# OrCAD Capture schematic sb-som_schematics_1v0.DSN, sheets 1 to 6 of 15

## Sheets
1 09. Ethernet & Camera: size C; title: SB-SOM    09. Ethernet & Camera; rev: 1.0; company: CompuLab Ltd.  (972) 4 8238567; note: 8000050000; note: P.O.Box 66; note: Nesher 36770, Israel
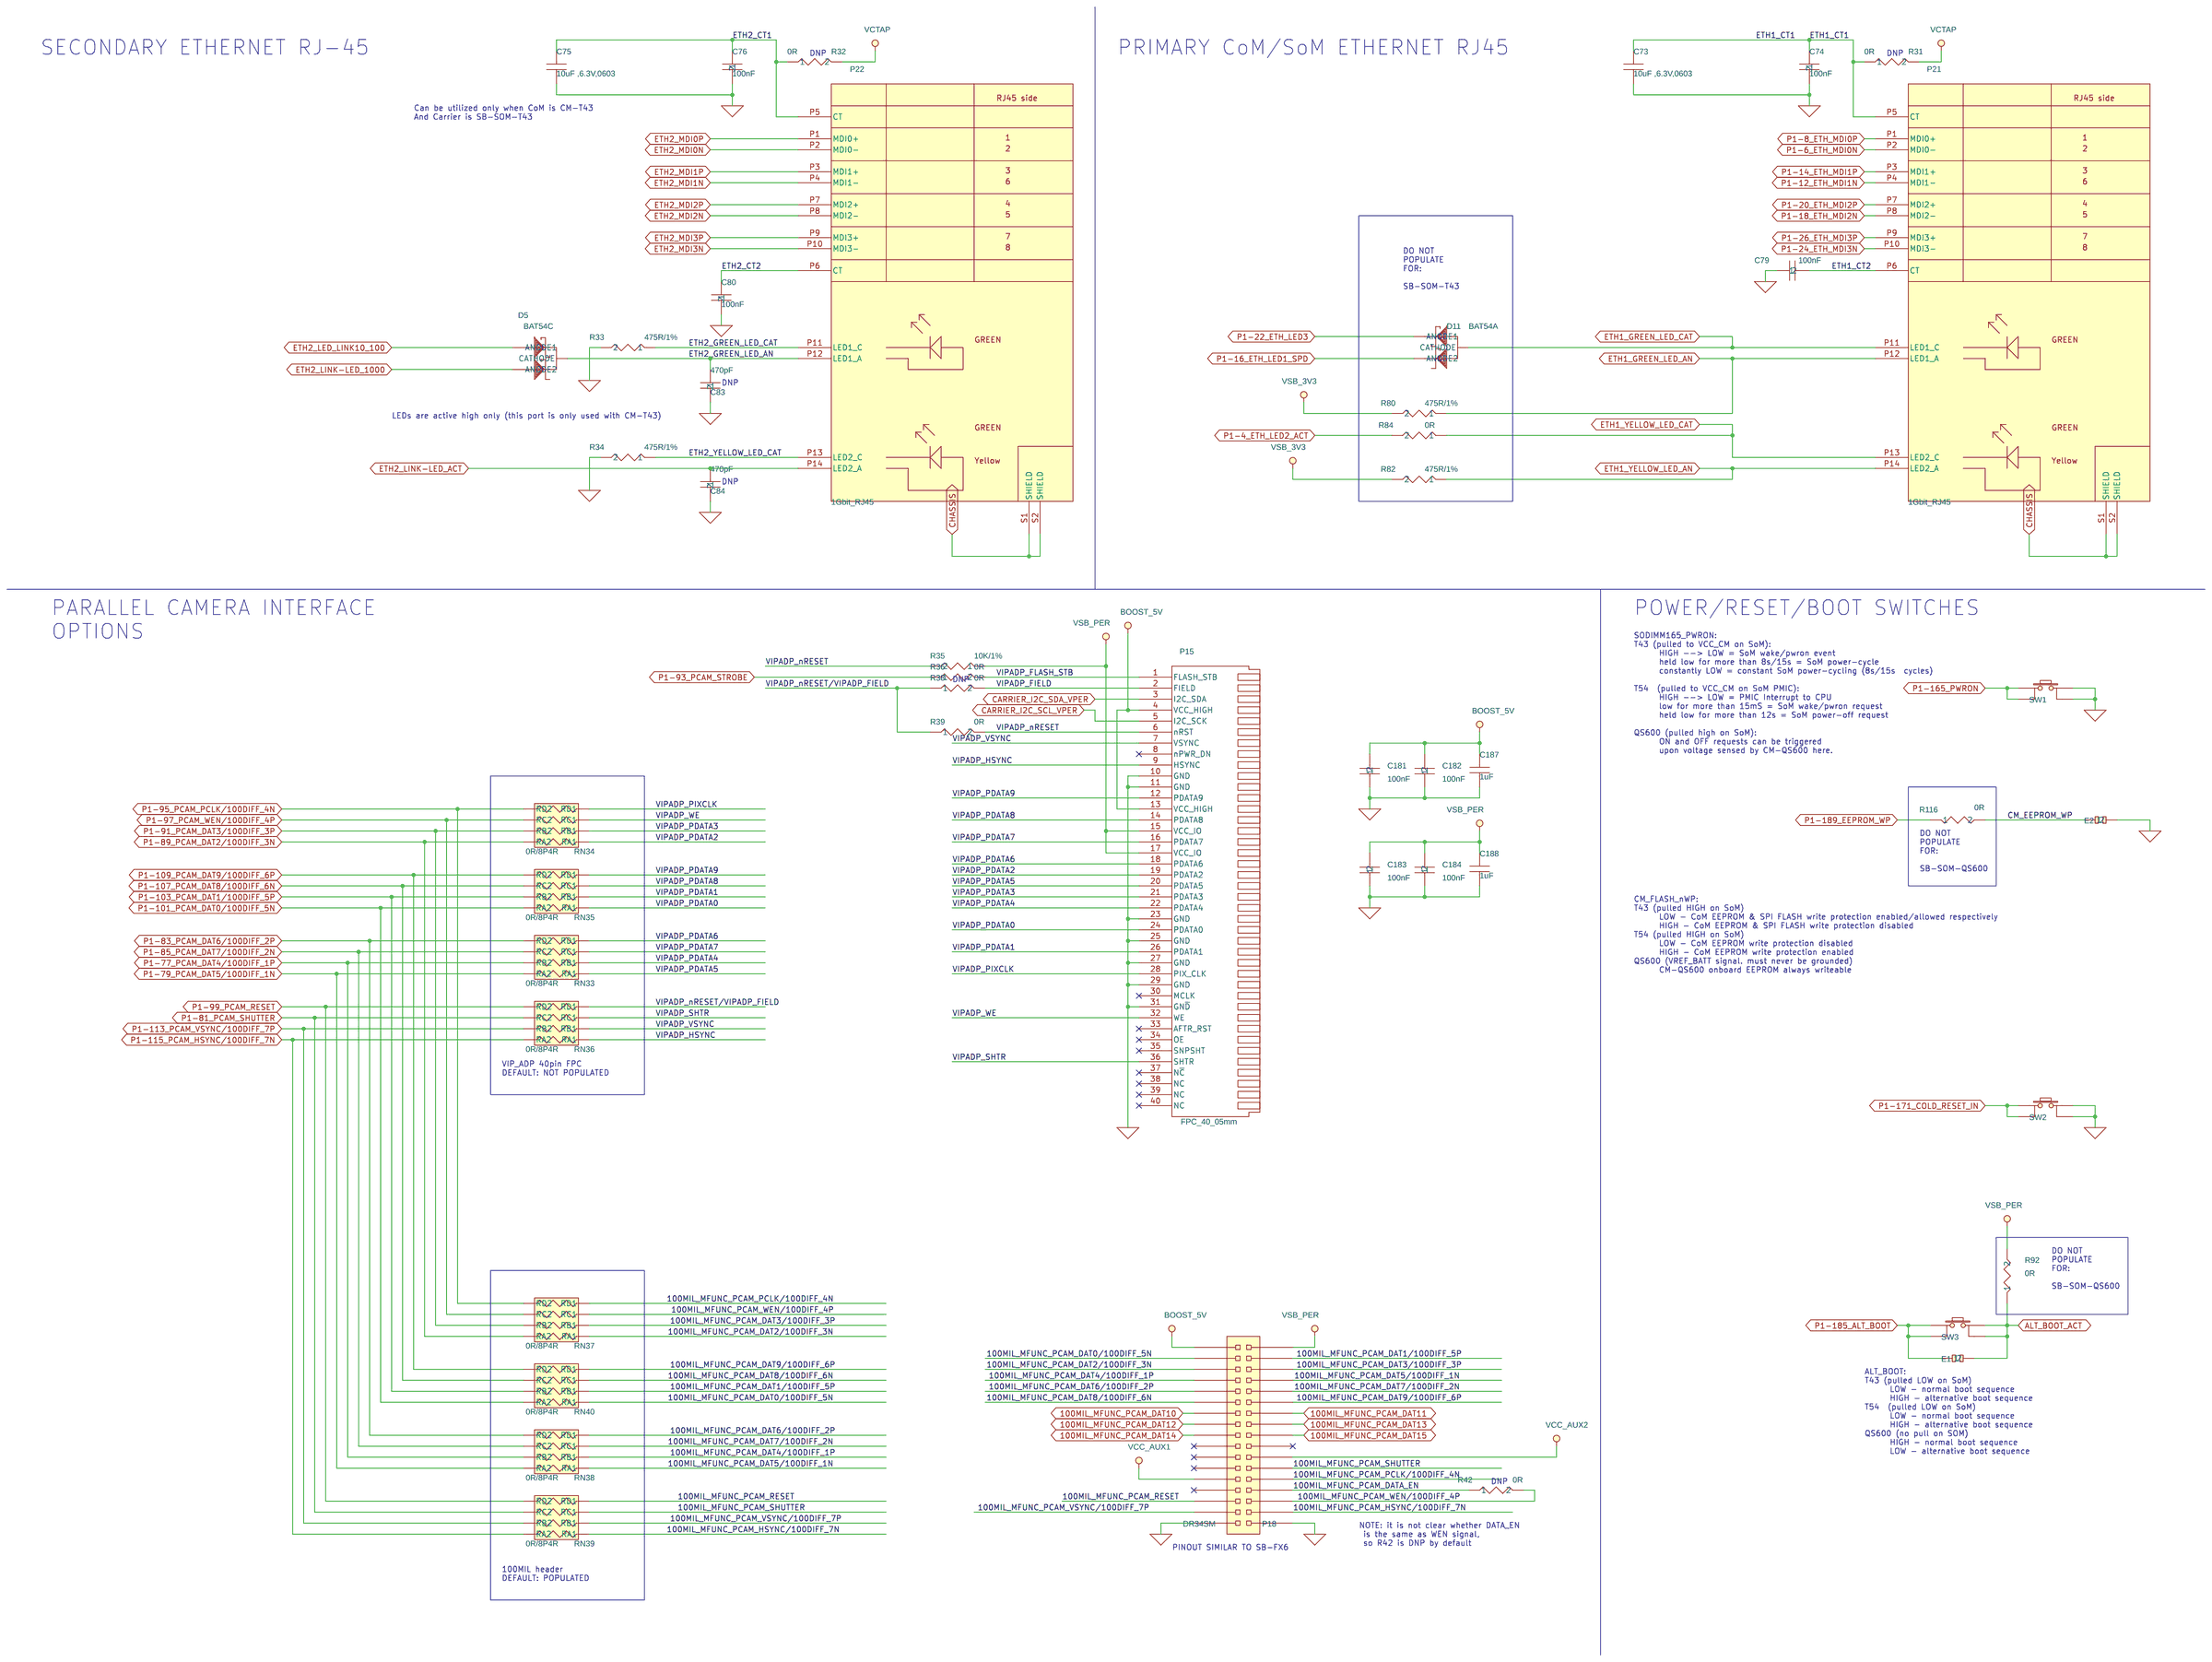
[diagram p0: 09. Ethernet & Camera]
2 02. Board Revision History: title: SB-SOM    02. Board Revision History
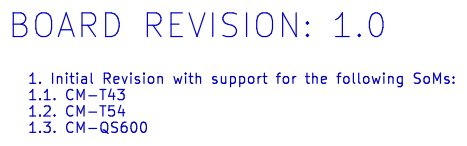
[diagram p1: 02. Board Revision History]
3 06. HDMI,  LVDS & CAN bus: size C; title: SB-SOM    06. HDMI,  LVDS & CAN bus
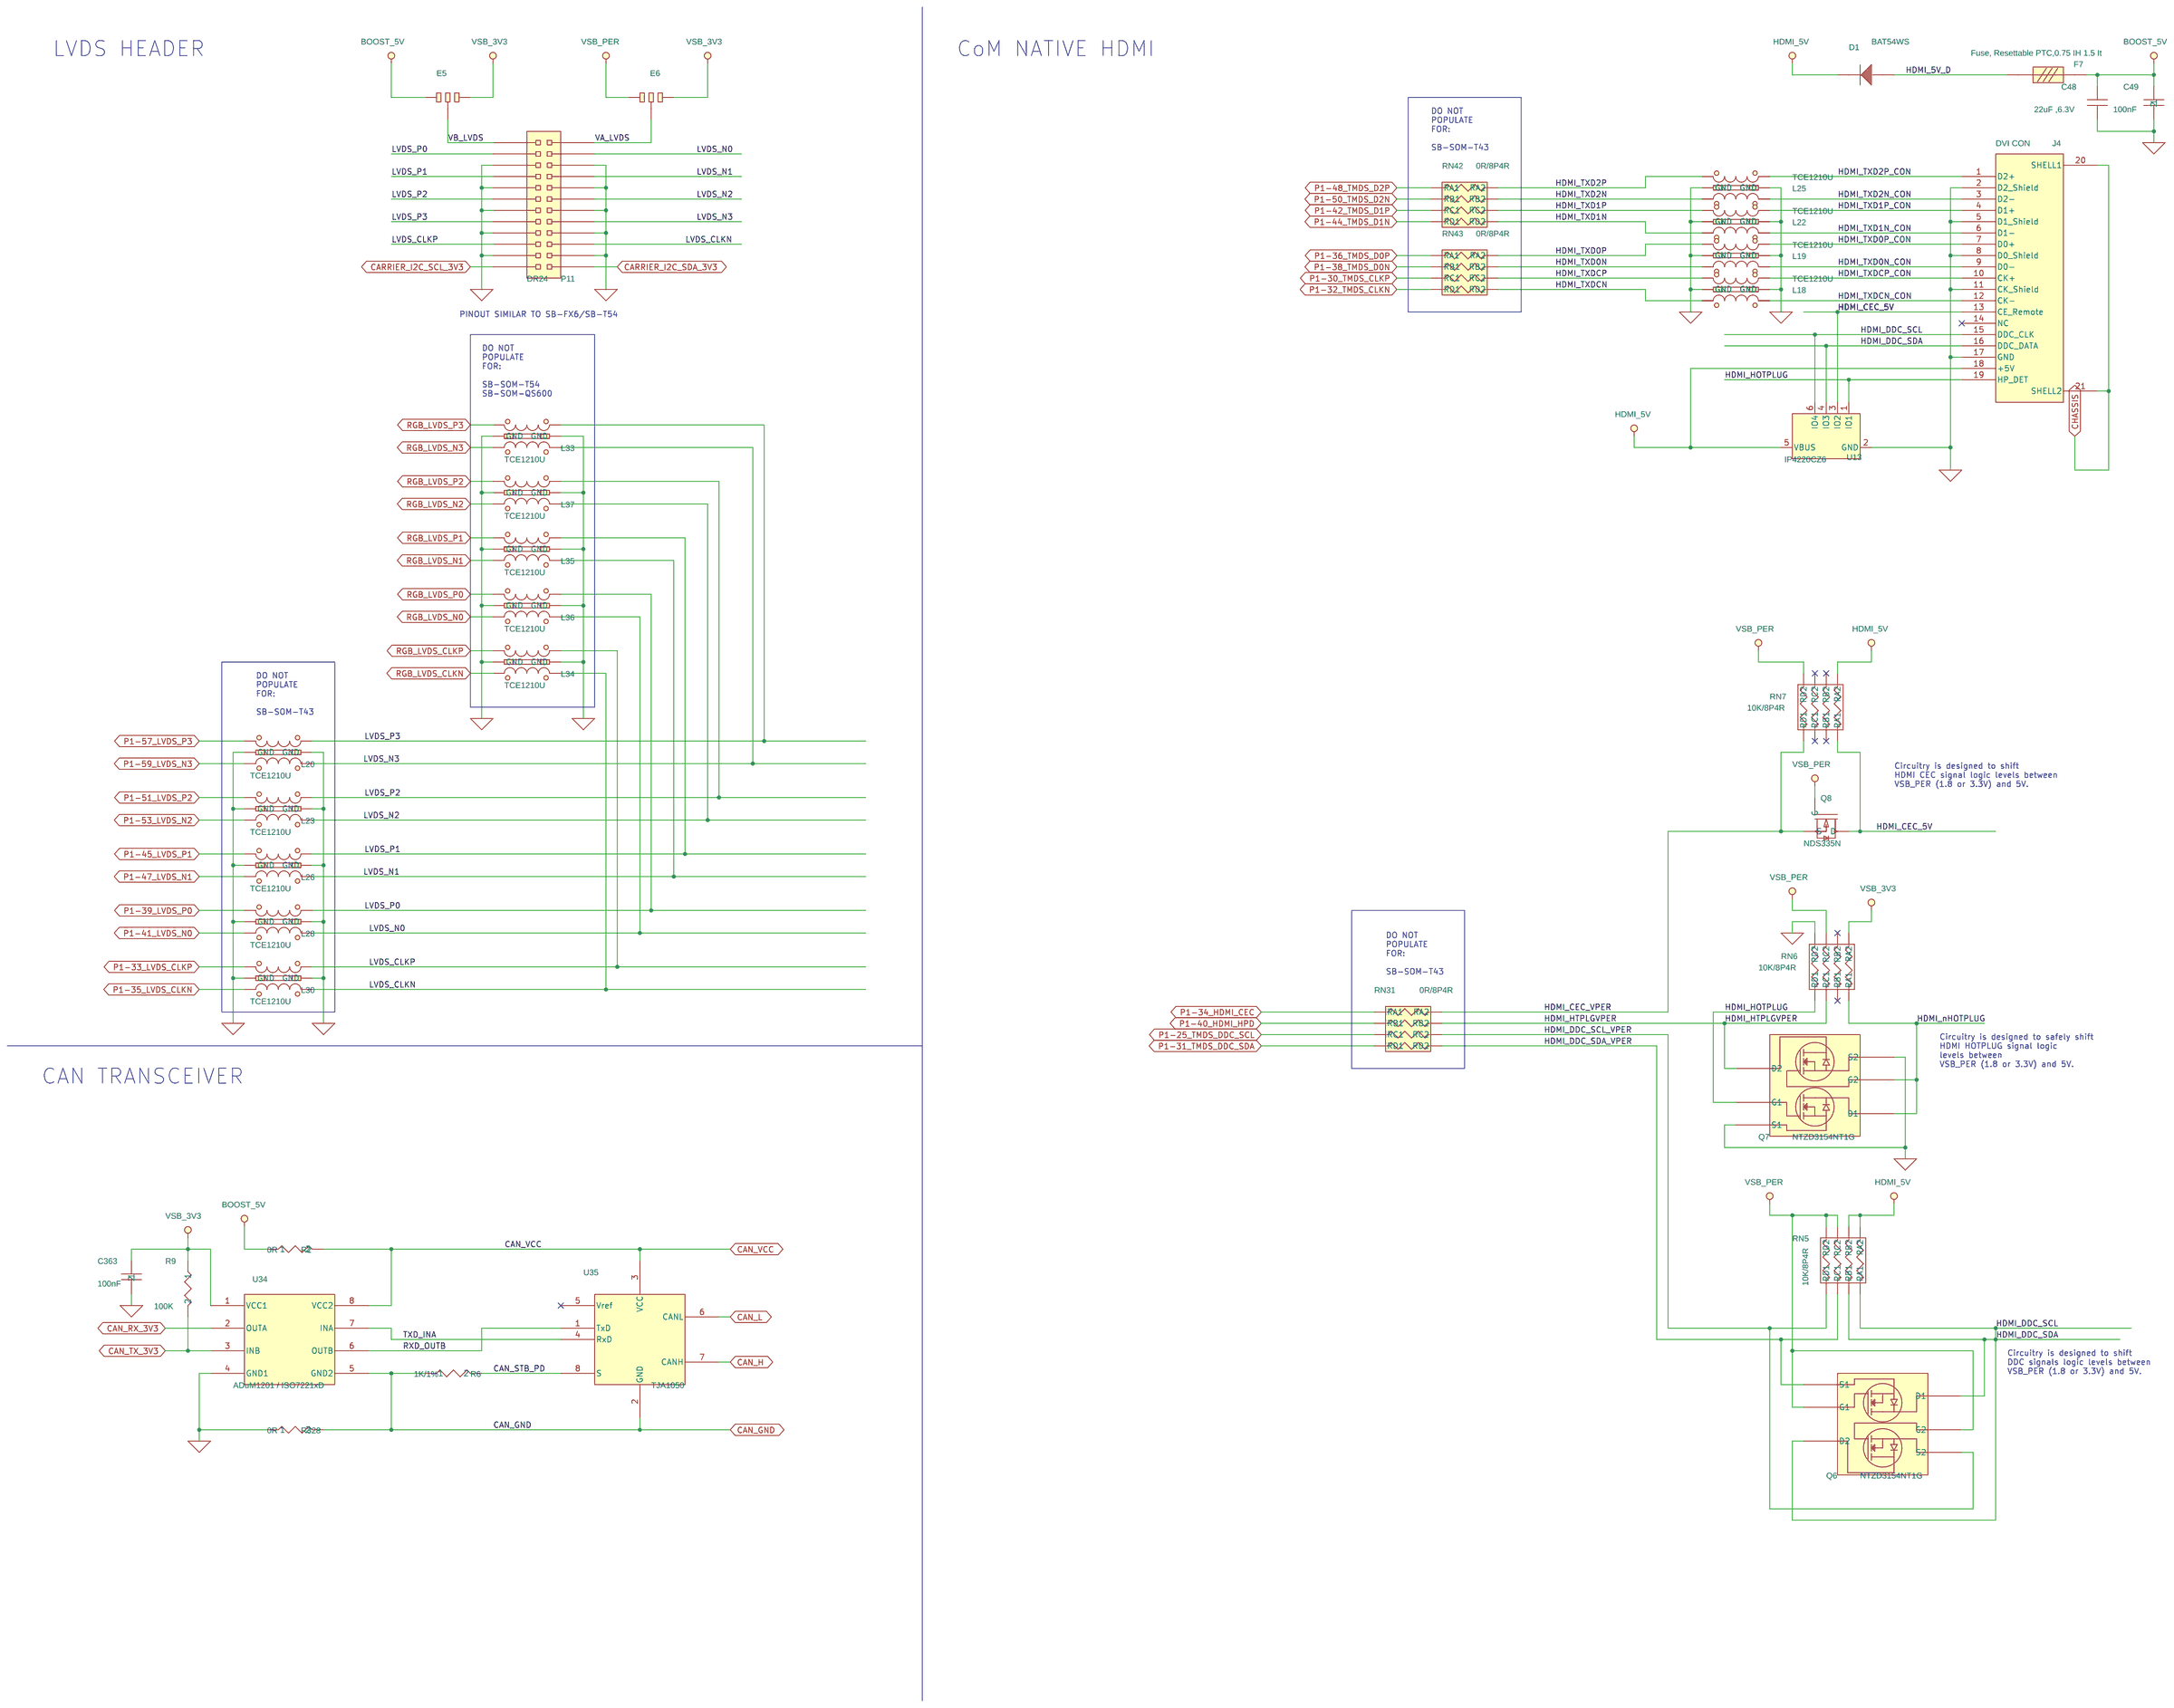
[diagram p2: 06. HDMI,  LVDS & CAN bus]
4 01. Index: size C; title: SB-SOM    01. Index
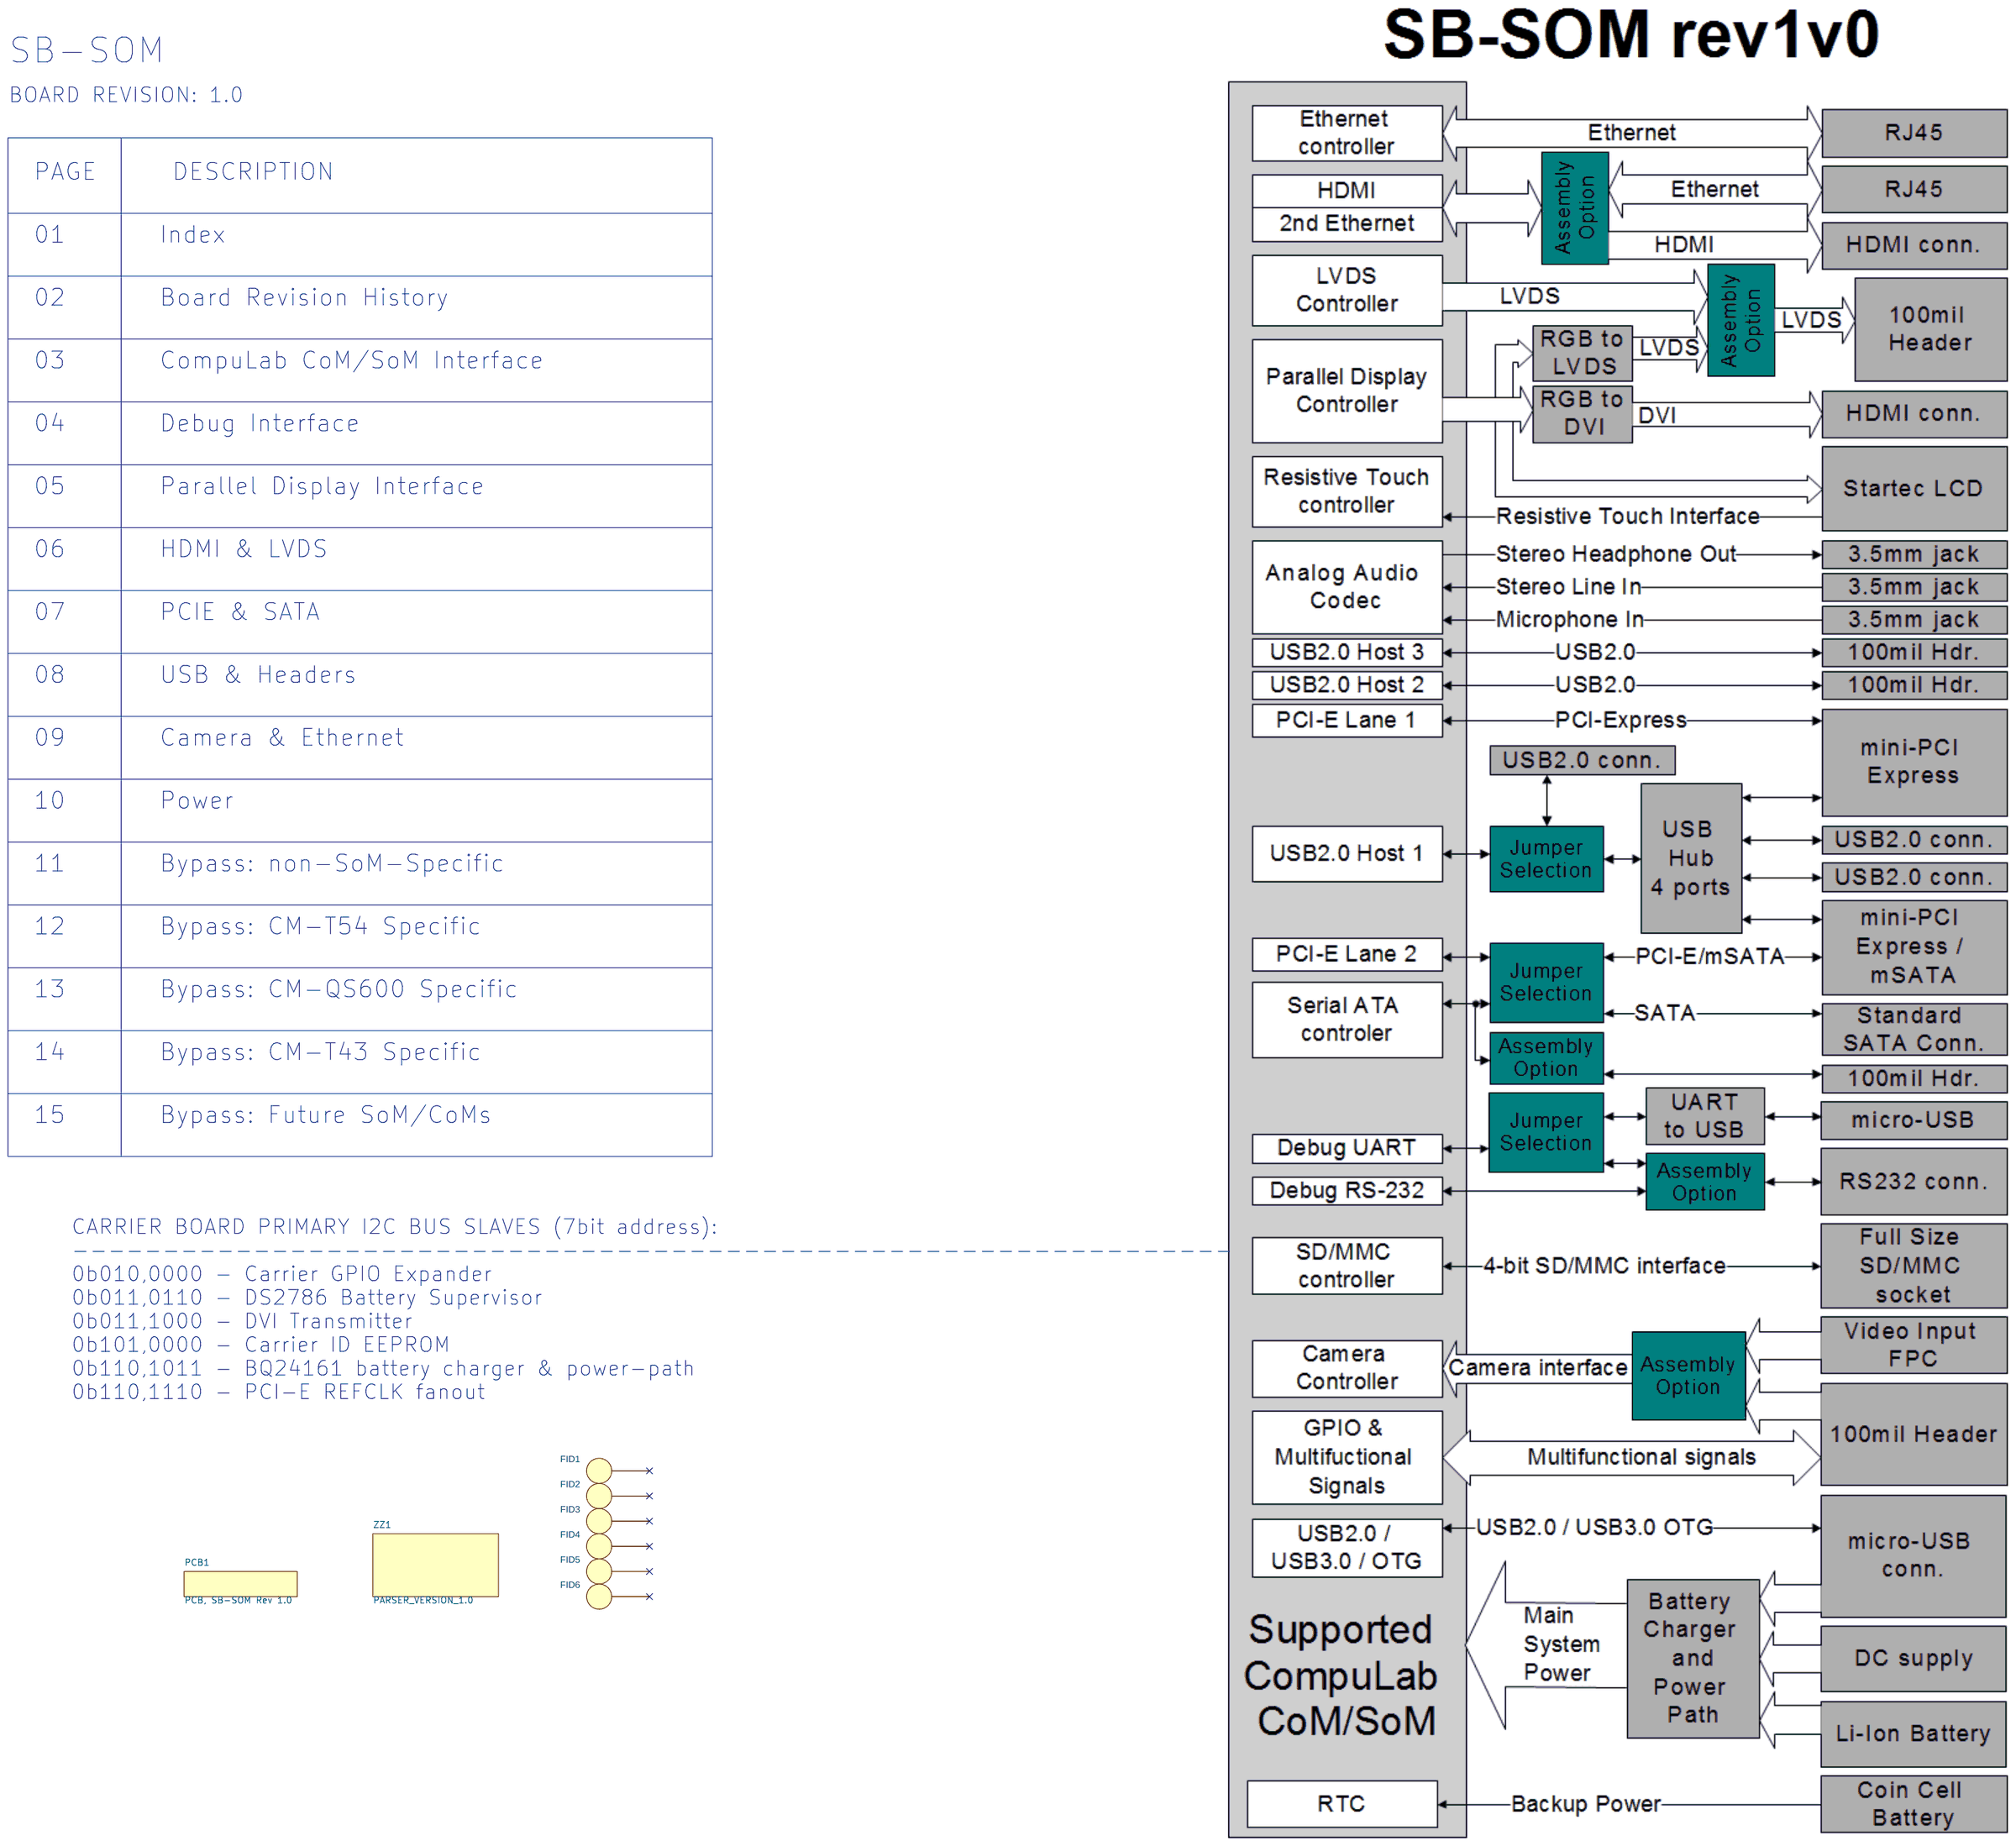
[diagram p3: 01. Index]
5 08. USB & Headers: size C; title: SB-SOM    08. USB & Headers
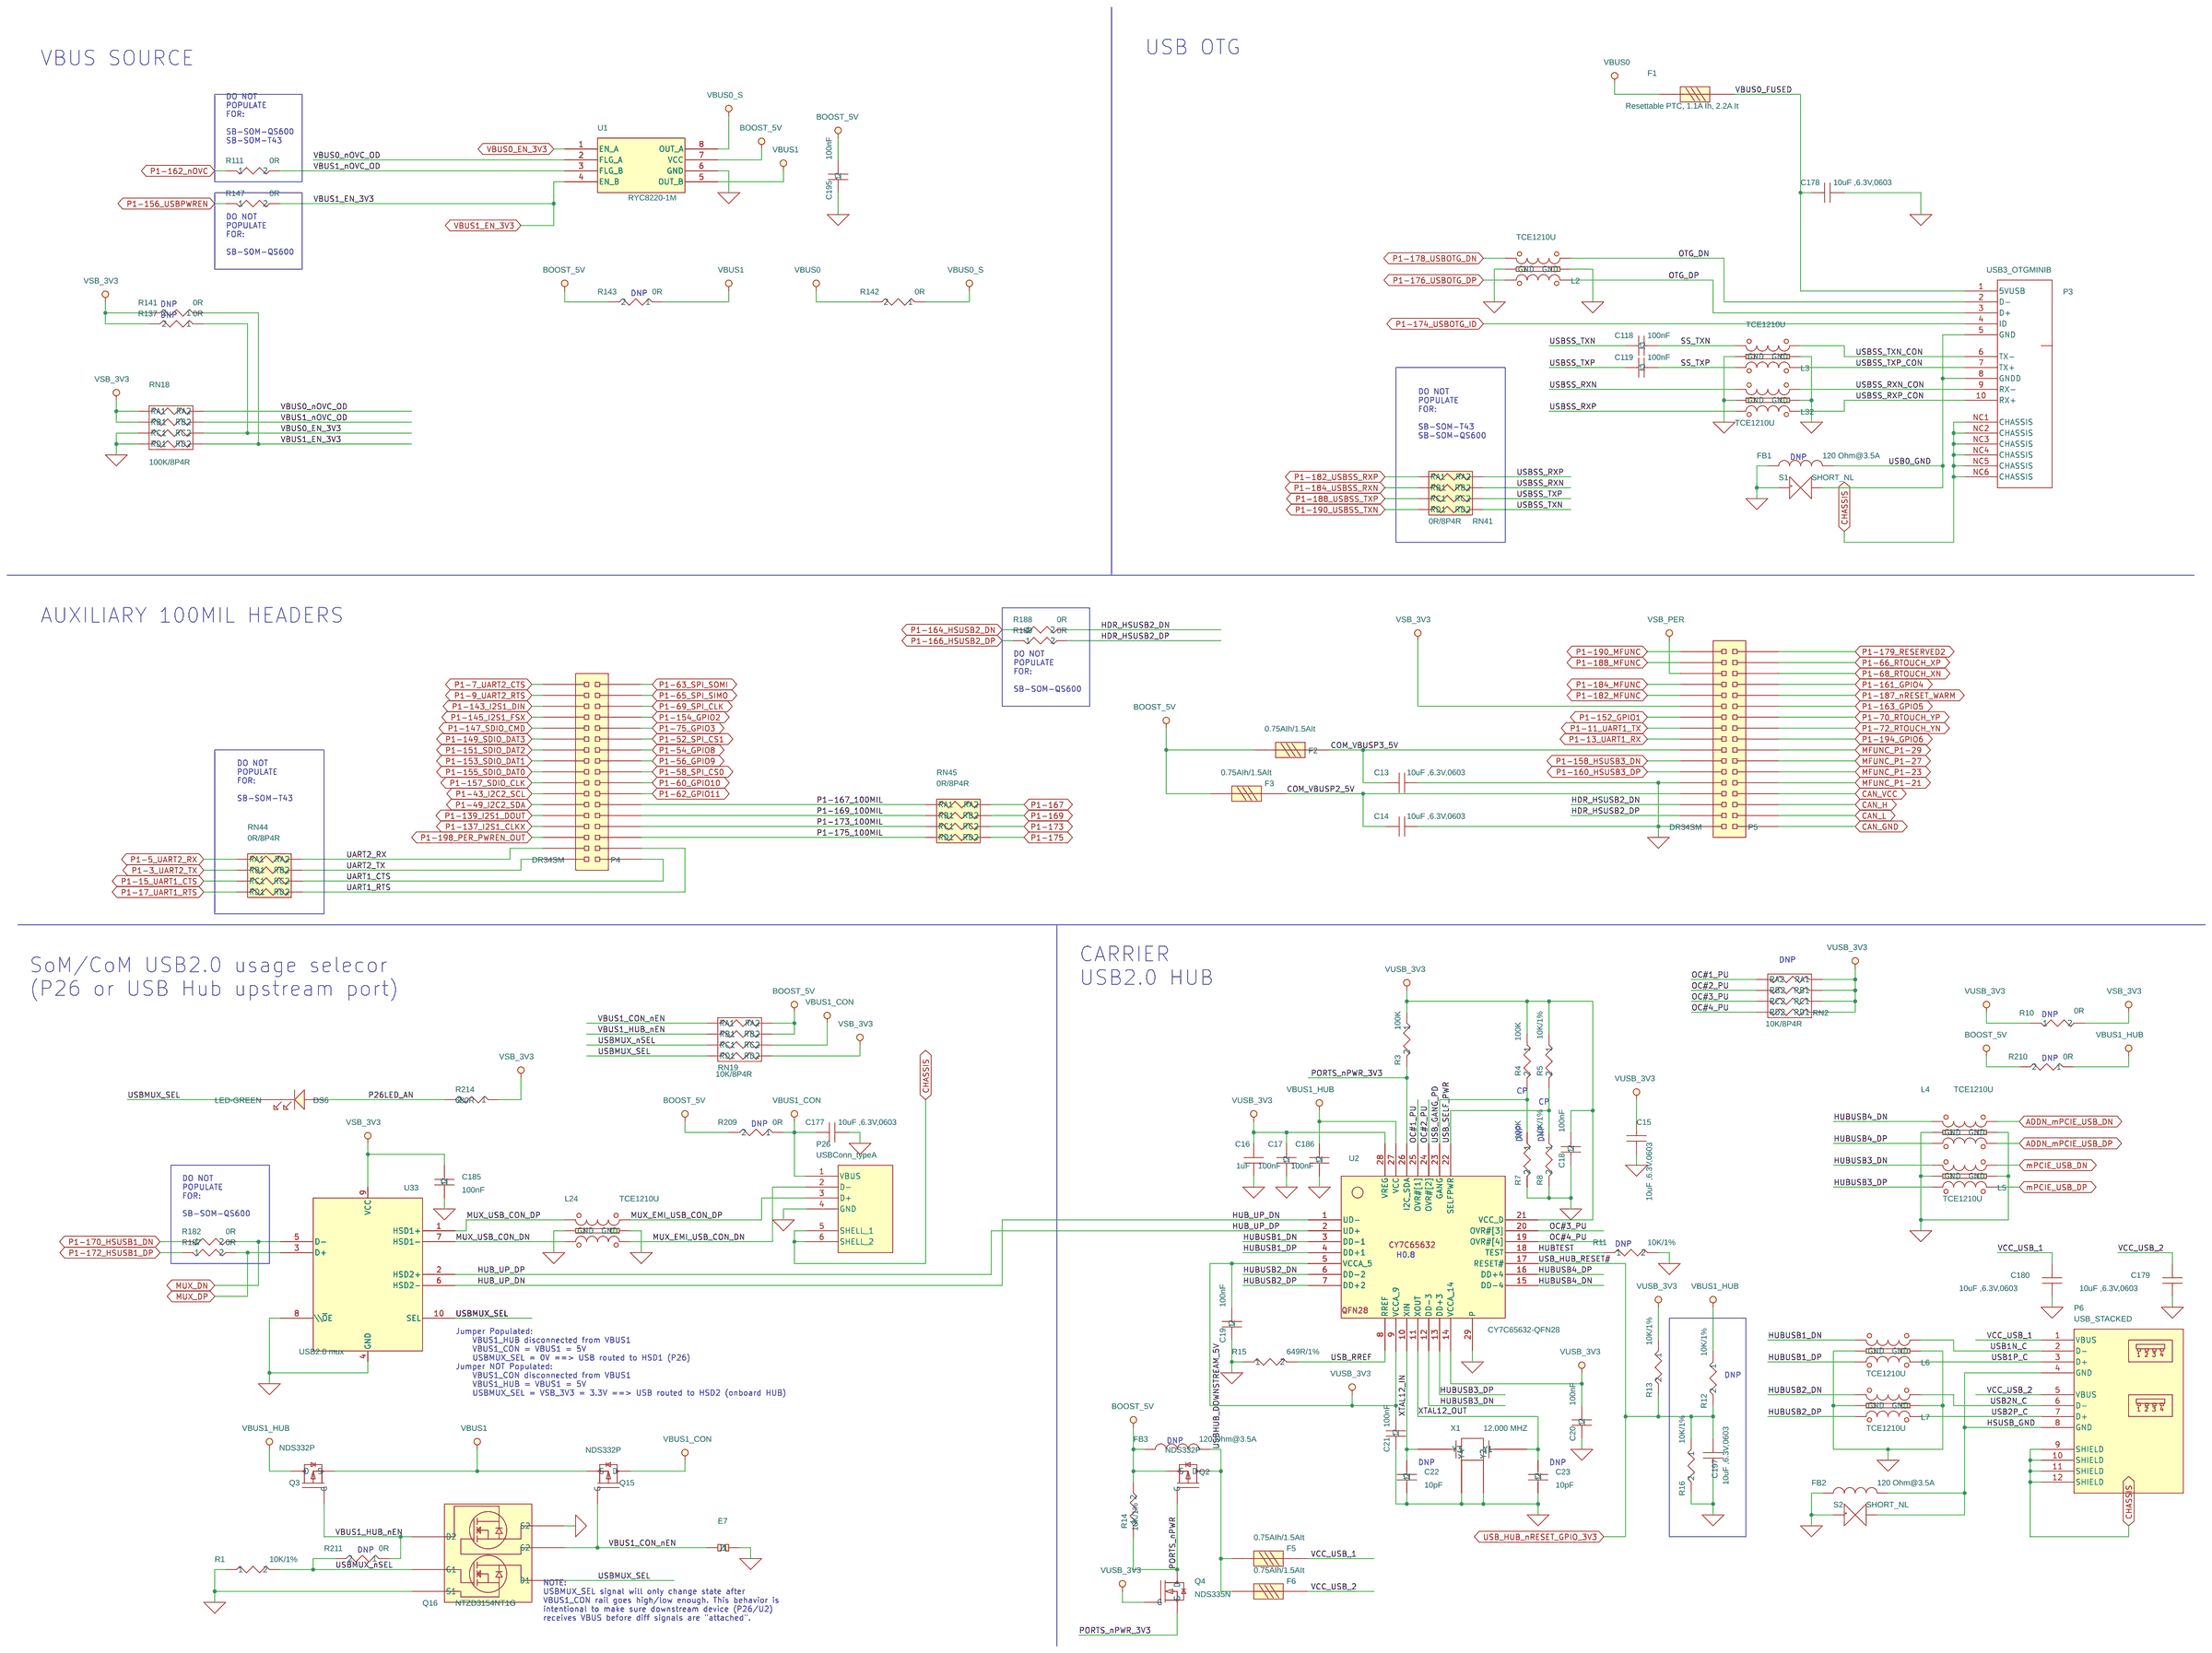
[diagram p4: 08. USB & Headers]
6 04. Debug Interface: size C; title: SB-SOM    04. Debug Interface
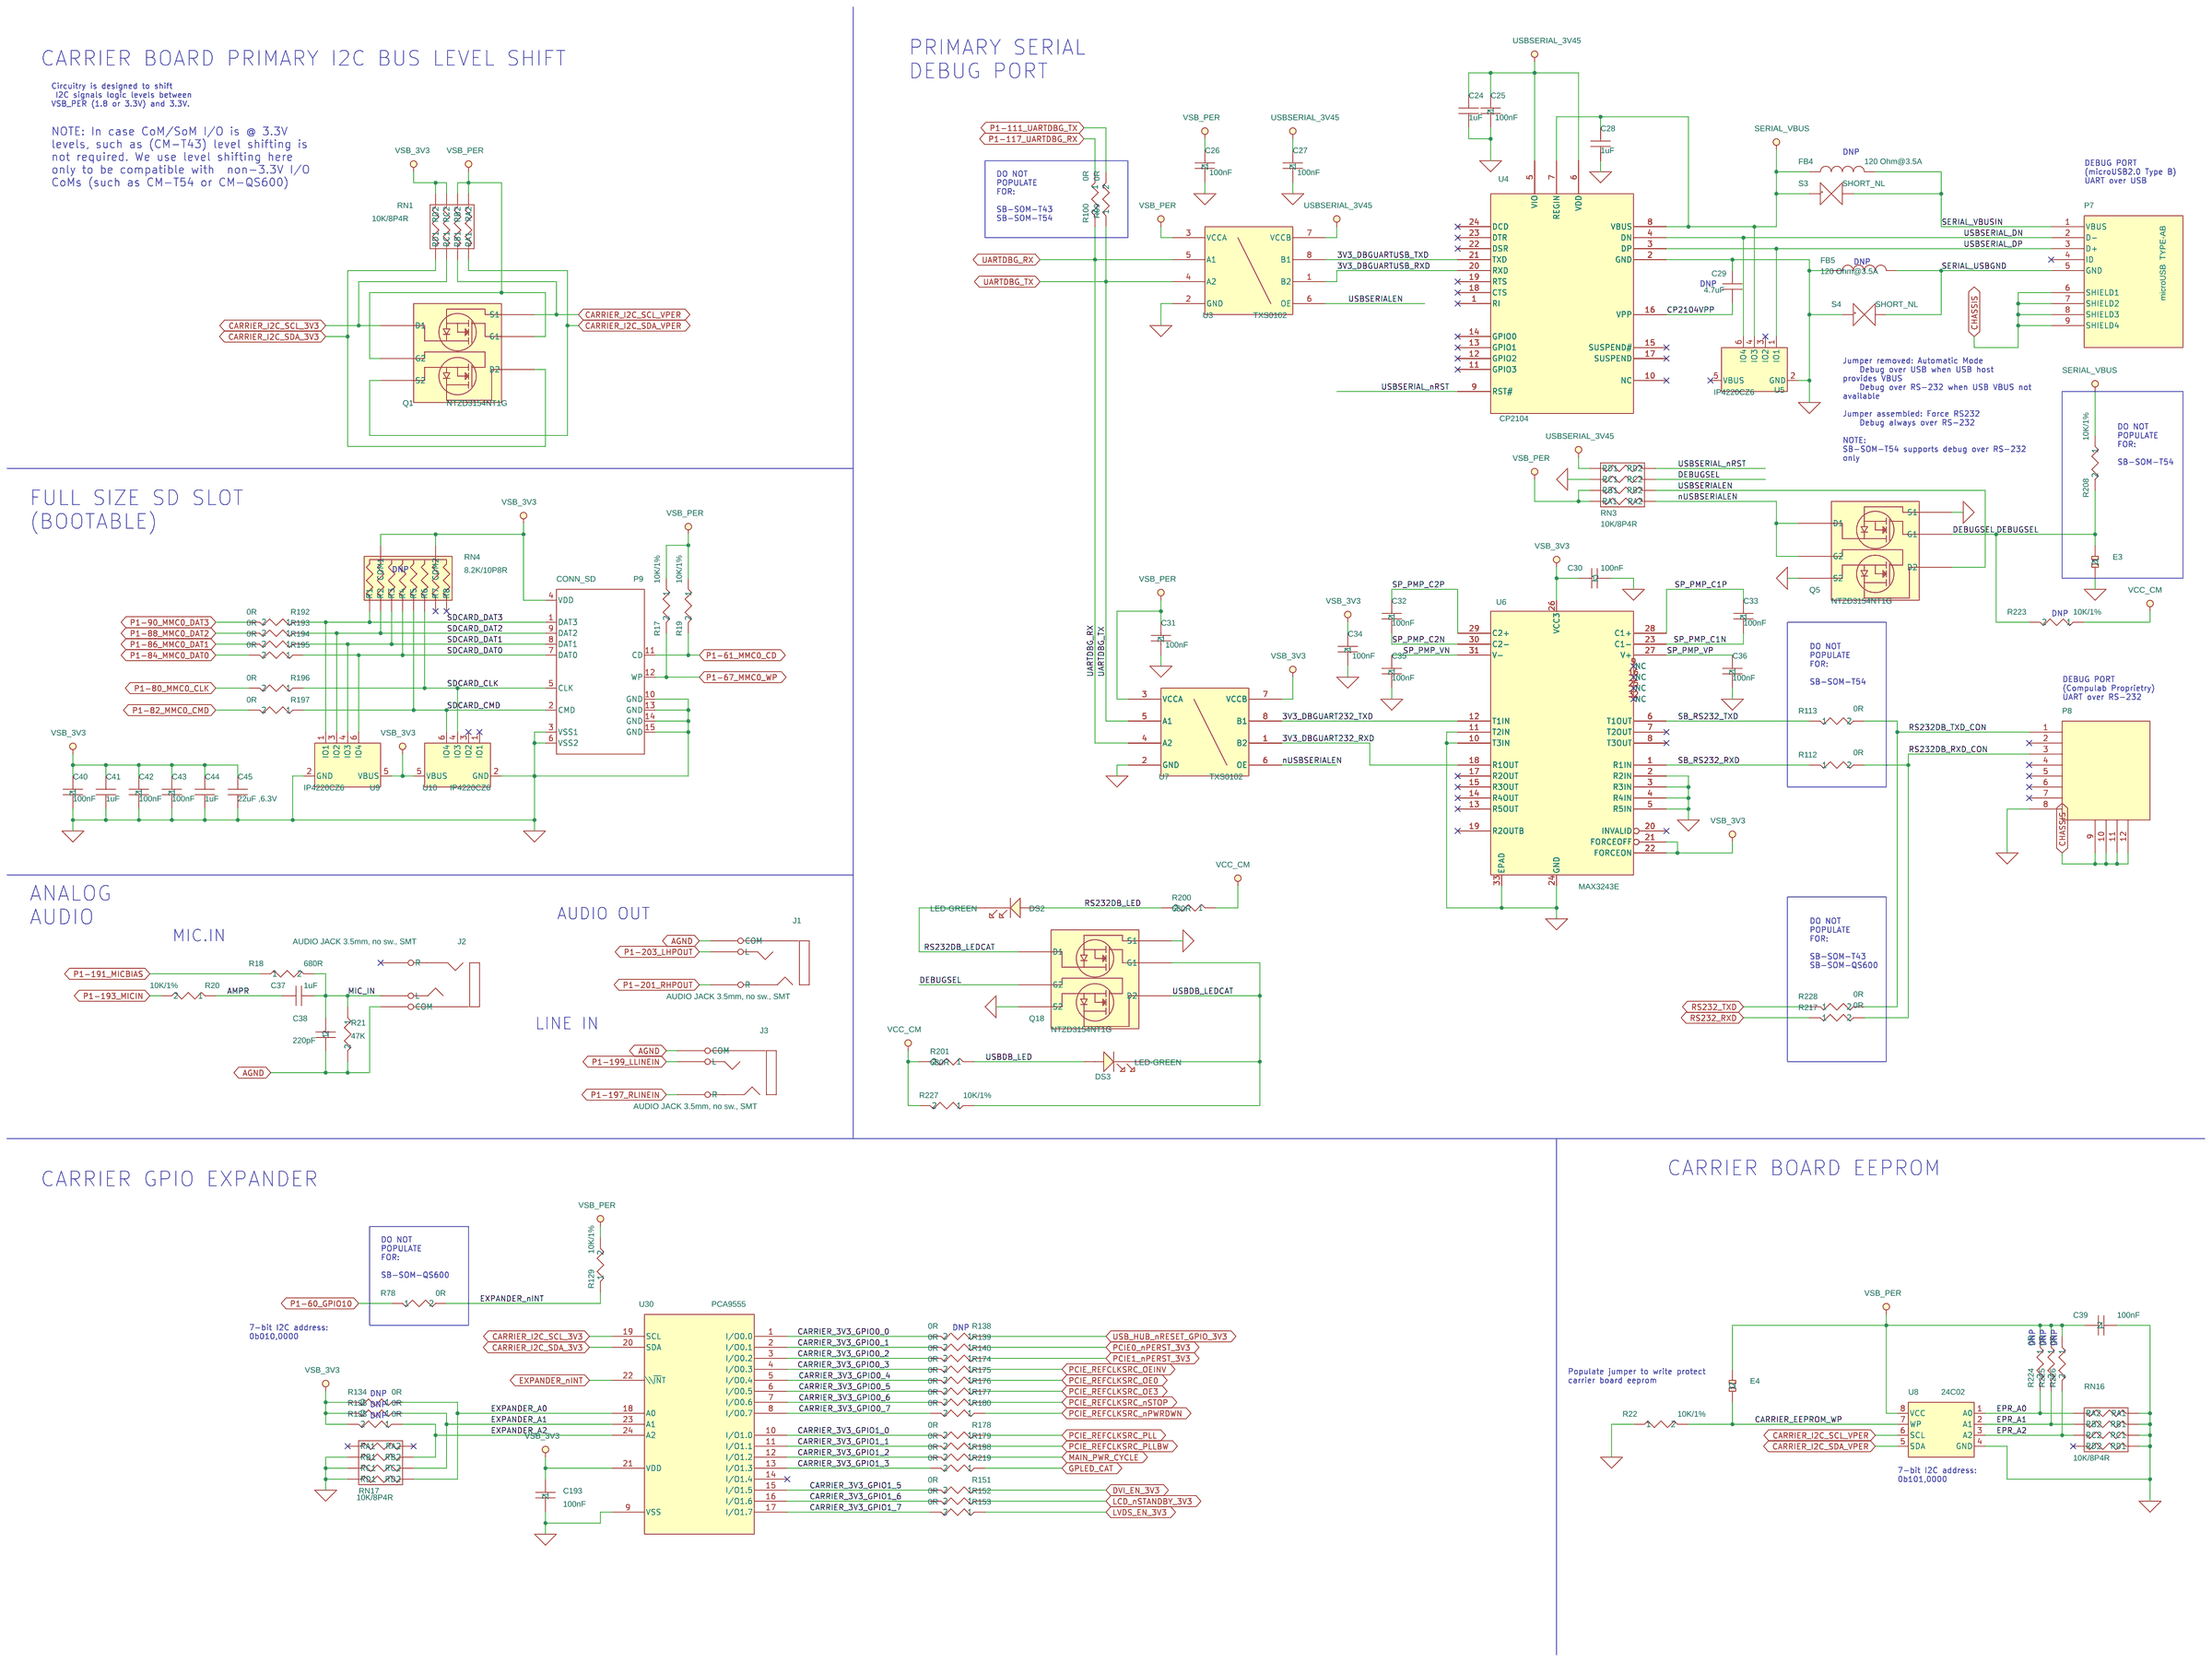
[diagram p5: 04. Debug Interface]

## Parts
sheet 01. Index
FID1  FIDUCIAL  [FIDUCIAL]
FID2  FIDUCIAL  [FIDUCIAL]
FID3  FIDUCIAL  [FIDUCIAL]
FID4  FIDUCIAL  [FIDUCIAL]
FID5  FIDUCIAL  [FIDUCIAL]
FID6  FIDUCIAL  [FIDUCIAL]
PCB1  PCB, SB-SOM Rev 1.0
ZZ1  PARSER_VERSION_1.0
sheet 04. Debug Interface
C24  1uF  [RC0402]
C25  100nF  [RC0402]
C26  100nF  [RC0402]
C27  100nF  [RC0402]
C28  1uF  [RC0402]
C29  4.7uF  [C0603-08]
C30  100nF  [RC0402]
C31  100nF  [RC0402]
C32  100nF  [RC0402]
C33  100nF  [RC0402]
C34  100nF  [RC0402]
C35  100nF  [RC0402]
C36  100nF  [RC0402]
C37  1uF  [RC0402]
C38  220pF  [RC0603]
C39  100nF  [RC0402]
C40  100nF  [RC0402]
C41  1uF  [RC0402]
C42  100nF  [RC0402]
C43  100nF  [RC0402]
C44  1uF  [RC0402]
C45  22uF ,6.3V  [RC0603]
C193  100nF  [RC0402]
DS2  LED-GREEN  [LED-1206]
DS3  LED-GREEN  [LED-1206]
E3  HDR1X2  [1X2THHDR]
E4  HDR1X2  [1X2THHDR]
FB4  120 Ohm@3.5A  [1206]
FB5  120 Ohm@3.5A  [1206]
J1  AUDIO JACK 3.5mm, no sw., SMT  [AJ35-3P-SM]
J2  AUDIO JACK 3.5mm, no sw., SMT  [AJ35-3P-SM]
J3  AUDIO JACK 3.5mm, no sw., SMT  [AJ35-3P-SM]
P7  microUSB  TYPE-AB  [MICRO-USB-AB-RA-SM]
P8  Ultra Mini Serial Connector  [UMS-8]
P9  CONN_SD  [SD-RA-SM]
Q1  NTZD3154NT1G  [SOT-563]
Q5  NTZD3154NT1G  [SOT-563]
Q18  NTZD3154NT1G  [SOT-563]
R17  10K/1%  [RC0402]
R18  680R  [RC0402]
R19  10K/1%  [RC0402]
R20  10K/1%  [RC0402]
R21  47K  [RC0402]
R22  10K/1%  [RC0402]
R78  0R  [RC0402]
R99  0R  [RC0402]
R100  0R  [RC0402]
R112  0R  [RC0402]
R113  0R  [RC0402]
R129  10K/1%  [RC0402]
R133  0R  [RC0402]
R134  0R  [RC0402]
R135  0R  [RC0402]
R138  0R  [RC0402]
R139  0R  [RC0402]
R140  0R  [RC0402]
R151  0R  [RC0402]
R152  0R  [RC0402]
R153  0R  [RC0402]
R174  0R  [RC0402]
R175  0R  [RC0402]
R176  0R  [RC0402]
R177  0R  [RC0402]
R178  0R  [RC0402]
R179  0R  [RC0402]
R180  0R  [RC0402]
R192  0R  [RC0402]
R193  0R  [RC0402]
R194  0R  [RC0402]
R195  0R  [RC0402]
R196  0R  [RC0402]
R197  0R  [RC0402]
R198  0R  [RC0402]
R200  680R  [RC0402]
R201  680R  [RC0402]
R208  10K/1%  [RC0402]
R217  0R  [RC0402]
R219  0R  [RC0402]
R223  10K/1%  [RC0402]
R224  0R  [RC0402]
R225  0R  [RC0402]
R226  0R  [RC0402]
R227  10K/1%  [RC0402]
R228  0R  [RC0402]
RN1  10K/8P4R  [RESNET8P0805]
RN3  10K/8P4R  [RESNET8P0805]
RN4  8.2K/10P8R  [RESNET10P1206]
RN16  10K/8P4R  [RESNET8P0805]
RN17  10K/8P4R  [RESNET8P0805]
S3  SHORT_NL  [JUMPER-VIA_1]
S4  SHORT_NL  [JUMPER-VIA_1]
U3  TXS0102  [MO-187DA-8]
U4  CP2104  [MO-220VGGD-8]
U5  IP4220CZ6  [SOT23-6L]
U6  MAX3243E  [QFN5x5-32]
U7  TXS0102  [MO-187DA-8]
U8  24C02  [MO-229VCED-2]
U9  IP4220CZ6  [SOT23-6L]
U10  IP4220CZ6  [SOT23-6L]
U30  PCA9555  [QFN4x4-24]
sheet 06. HDMI,  LVDS & CAN bus
C48  22uF ,6.3V  [RC0603]
C49  100nF  [RC0402]
C363  100nF  [RC0402]
D1  BAT54WS  [SOD-323]
E5  JP3  [1X3THHDR]
E6  JP3  [1X3THHDR]
F7  Fuse, Resettable PTC,0.75 IH 1.5 It  [FUSE-1206]
J4  DVI CON  [HDMI-A19-RASM]
L18  TCE1210U  [EMI1012-ESD]
L19  TCE1210U  [EMI1012-ESD]
L20  TCE1210U  [EMI1012-ESD]
L22  TCE1210U  [EMI1012-ESD]
L23  TCE1210U  [EMI1012-ESD]
L25  TCE1210U  [EMI1012-ESD]
L26  TCE1210U  [EMI1012-ESD]
L28  TCE1210U  [EMI1012-ESD]
L30  TCE1210U  [EMI1012-ESD]
L33  TCE1210U  [EMI1012-ESD]
L34  TCE1210U  [EMI1012-ESD]
L35  TCE1210U  [EMI1012-ESD]
L36  TCE1210U  [EMI1012-ESD]
L37  TCE1210U  [EMI1012-ESD]
P11  DR24  [2X12THHDR]
Q6  NTZD3154NT1G  [SOT-563]
Q7  NTZD3154NT1G  [SOT-563]
Q8  NDS335N  [SOT23]
R2  0R  [RC0402]
R6  1K/1%  [RC0402]
R9  100K  [RC0402]
R328  0R  [RC0402]
RN5  10K/8P4R  [RESNET8P0805]
RN6  10K/8P4R  [RESNET8P0805]
RN7  10K/8P4R  [RESNET8P0805]
RN31  0R/8P4R  [RESNET8P0805]
RN42  0R/8P4R  [RESNET8P0805]
RN43  0R/8P4R  [RESNET8P0805]
U13  IP4220CZ6  [SOT23-6L]
U34  ADuM1201 / ISO7221xD  [SO-8-150]
U35  TJA1050  [SO-8-150]
sheet 08. USB & Headers
C13  10uF ,6.3V,0603  [RC0603]
C14  10uF ,6.3V,0603  [RC0603]
C15  10uF ,6.3V,0603  [RC0603]
C16  1uF  [RC0402]
C17  100nF  [RC0402]
C18  100nF  [RC0402]
C19  100nF  [RC0402]
C20  100nF  [RC0402]
C21  100nF  [RC0402]
C22  10pF  [RC0402]
C23  10pF  [RC0402]
C118  100nF  [RC0402]
C119  100nF  [RC0402]
C177  10uF ,6.3V,0603  [C0603-08]
C178  10uF ,6.3V,0603  [C0603-08]
C179  10uF ,6.3V,0603  [C0603-08]
C180  10uF ,6.3V,0603  [C0603-08]
C185  100nF  [RC0402]
C186  100nF  [RC0402]
C195  100nF  [RC0402]
C197  10uF ,6.3V,0603  [C0603-08]
DS6  LED-GREEN  [LED-1206]
E7  HDR1X2  [1X2THHDR]
F1  Resettable PTC, 1.1A Ih, 2.2A It  [FUSE-1206]
F2  0.75AIh/1.5AIt  [FUSE-1206]
F3  0.75AIh/1.5AIt  [FUSE-1206]
F5  0.75AIh/1.5AIt  [FUSE-1206]
F6  0.75AIh/1.5AIt  [FUSE-1206]
FB1  120 Ohm@3.5A  [1206]
FB2  120 Ohm@3.5A  [1206]
FB3  120 Ohm@3.5A  [1206]
L2  TCE1210U  [EMI1012-ESD]
L3  TCE1210U  [EMI1012-ESD]
L4  TCE1210U  [EMI1012-ESD]
L5  TCE1210U  [EMI1012-ESD]
L6  TCE1210U  [EMI1012-ESD]
L7  TCE1210U  [EMI1012-ESD]
L24  TCE1210U  [EMI1012-ESD]
L32  TCE1210U  [EMI1012-ESD]
P3  USB3_OTGMINIB  [MICRO-USB3-AB-RA-SM]
P4  DR34SM  [2X17SMHDR]
P5  DR34SM  [2X17SMHDR]
P6  USB_STACKED  [USB-2XA-TH]
P26  USBConn_typeA  [USB-A-SM]
Q2  NDS332P  [SOT23]
Q3  NDS332P  [SOT23]
Q4  NDS335N  [SOT23]
Q15  NDS332P  [SOT23]
Q16  NTZD3154NT1G  [SOT-563]
R1  10K/1%  [RC0402]
R3  100K  [RC0402]
R4  100K  [RC0402]
R5  10K/1%  [RC0402]
R7  100K  [RC0402]
R8  10K/1%  [RC0402]
R10  0R  [RC0402]
R11  10K/1%  [RC0402]
R12  10K/1%  [RC0402]
R13  10K/1%  [RC0402]
R14  10K/1%  [RC0402]
R15  649R/1%  [RC0402]
R16  10K/1%  [RC0402]
R111  0R  [RC0402]
R137  0R  [RC0402]
R141  0R  [RC0402]
R142  0R  [RC0402]
R143  0R  [RC0402]
R147  0R  [RC0402]
R182  0R  [RC0402]
R187  0R  [RC0402]
R188  0R  [RC0402]
R189  0R  [RC0402]
R209  0R  [RC0402]
R210  0R  [RC0402]
R211  0R  [RC0402]
R214  680R  [RC0402]
RN2  10K/8P4R  [RESNET8P0805]
RN18  100K/8P4R  [RESNET8P0805]
RN19  10K/8P4R  [RESNET8P0805]
RN41  0R/8P4R  [RESNET8P0805]
RN44  0R/8P4R  [RESNET8P0805]
RN45  0R/8P4R  [RESNET8P0805]
S1  SHORT_NL  [JUMPER-VIA_1]
S2  SHORT_NL  [JUMPER-VIA_1]
U1  RYC8220-1M  [SO-8-150]
U2  CY7C65632-QFN28  [QFN28]
U33  USB2.0 mux  [MO-255U1418E]
X1  12.000 MHZ  [OSC3225]
sheet 09. Ethernet & Camera
C73  10uF ,6.3V,0603  [RC0603]
C74  100nF  [RC0402]
C75  10uF ,6.3V,0603  [RC0603]
C76  100nF  [RC0402]
C79  100nF  [RC0402]
C80  100nF  [RC0402]
C83  470pF  [RC0603]
C84  470pF  [RC0603]
C181  100nF  [RC0402]
C182  100nF  [RC0402]
C183  100nF  [RC0402]
C184  100nF  [RC0402]
C187  1uF  [RC0402]
C188  1uF  [RC0402]
D5  BAT54C  [SOT23]
D11  BAT54A  [SOT23]
E1  HDR1X2  [1X2THHDR]
E2  HDR1X2  [1X2THHDR]
P15  FPC_40_05mm  [FPC05SM40-1]
P18  DR34SM  [2X17SMHDR]
P21  1Gbit_RJ45  [DUSBRJ-1G]
P22  1Gbit_RJ45  [DUSBRJ-1G]
R31  0R  [RC0402]
R32  0R  [RC0402]
R33  475R/1%  [RC0402]
R34  475R/1%  [RC0402]
R35  10K/1%  [RC0402]
R36  0R  [RC0402]
R38  0R  [RC0402]
R39  0R  [RC0402]
R42  0R  [RC0402]
R80  475R/1%  [RC0402]
R82  475R/1%  [RC0402]
R84  0R  [RC0402]
R92  0R  [RC0402]
R116  0R  [RC0402]
RN33  0R/8P4R  [RESNET8P0805]
RN34  0R/8P4R  [RESNET8P0805]
RN35  0R/8P4R  [RESNET8P0805]
RN36  0R/8P4R  [RESNET8P0805]
RN37  0R/8P4R  [RESNET8P0805]
RN38  0R/8P4R  [RESNET8P0805]
RN39  0R/8P4R  [RESNET8P0805]
RN40  0R/8P4R  [RESNET8P0805]
SW1  PushB  [TACTSW6x6SM]
SW2  PushB  [TACTSW6x6SM]
SW3  PushB  [TACTSW6x6SM]

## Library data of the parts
FID1-FID6 = TESTPOINT_2: CLABCONF0: DNP
PCB1 = PCB,_EM-X270_Rev_1_0.1: CLABCONF0: = SB-SOM; P/N: 188C02760
ZZ1 = PARSER_VERSION_1_1.0
C24 C28 C37 C41 C44 C187 C188 = 1uF,X5R,6.3V,0402: CLABCONF0: = SB-SOM
C25 = 100nF,_10V,_X7R,_10%,_0402_1: CLABCONF0: = SB-SOM
C17 C26 = 100nF,_10V,_X7R,_10%,_0402_2: CLABCONF0: = SB-SOM
C27 = 100nF,_10V,_X7R,_10%,_0402_13: CLABCONF0: = SB-SOM
C29 = 4.7uF,_6.3V,_X5R,_20%,_0603: CLABCONF0: DNP
C18 C30 = 100nF,_10V,_X7R,_10%,_0402: CLABCONF0: = SB-SOM
C21 C31 = 100nF,_10V,_X7R,_10%,_0402_9: CLABCONF0: = SB-SOM
C20 C32 = 100nF,_10V,_X7R,_10%,_0402_3: CLABCONF0: = SB-SOM
C33 = 100nF,_10V,_X7R,_10%,_0402_7: CLABCONF0: = SB-SOM
C34 C118 = 100nF,_10V,_X7R,_10%,_0402_4: CLABCONF0: = SB-SOM
C35 C119 = 100nF,_10V,_X7R,_10%,_0402_8: CLABCONF0: = SB-SOM
C36 C195 = 100nF,_10V,_X7R,_10%,_0402_5: CLABCONF0: = SB-SOM
C38 = 220pF,50V,NPO,0603: CLABCONF0: = SB-SOM
C39 = 100nF,_10V,_X7R,_10%,_0402_11: CLABCONF0: = SB-SOM
C40 = 100nF,_10V,_X7R,_10%,_0402_12: CLABCONF0: = SB-SOM
C42 = 100nF,_10V,_X7R,_10%,_0402_14: CLABCONF0: = SB-SOM
C43 = 100nF,_10V,_X7R,_10%,_0402_10: CLABCONF0: = SB-SOM
C45 = 22uF,6.3V,X5R: CLABCONF0: = SB-SOM; P/N: 151B22610S
C19 C193 = 100nF,_10V,_X7R,_10%,_0402_6: CLABCONF0: = SB-SOM
DS2 DS3 DS6 = LED-GREEN_1206_3: CLABCONF0: = SB-SOM
E3 = HDR_1x2_100MIL_TH_JUMPER: CLABCONF0: = SB-SOM AND NOT T54
E2 E4 = HDR_1x2_100MIL_TH_JUMPER_1: CLABCONF0: = SB-SOM
FB3 FB4 = Ferrite_bead_,_120_Ohm@3A: CLABCONF0: DNP
FB5 = Ferrite_bead_,_120_Ohm@3A_1: CLABCONF0: DNP
J1-J3 = AUDIO_JACK_3.5mm,_no_sw.,_SMT: CLABCONF0: = SB-SOM
P7 = Conn.,_Micro-USB,_B-Type: CLABCONF0: = SB-SOM; P/N: 180K00502S
P8 = Ultra_Mini_Serial_Connector: CLABCONF0: = SB-SOM
P9 = SDIO_SLOT: CLABCONF0: = SB-SOM
Q1 Q5 Q16 Q18 = MOSFET_N_DUAL_0_0.4A_20V: CLABCONF0: = SB-SOM
R5 R17 = 10K,1%,0402,1_16W_2: CLABCONF0: = SB-SOM
R18 R214 = 47K,_0402: CLABCONF0: = SB-SOM; P/N: 161C68001S
R19 = 10K,1%,0402,1_16W_7: CLABCONF0: = SB-SOM
R20 R35 = 10K,1%,0402,1_16W: CLABCONF0: = SB-SOM
R21 = 47K,_0402_2: CLABCONF0: = SB-SOM
R22 = 10K,1%,0402,1_16W_3: CLABCONF0: = SB-SOM
R78 = 0R,_0402_33: CLABCONF0: = SB-SOM AND NOT QS600
R99 = 0R,_0402_20: CLABCONF0: = SB-SOM AND NOT T43 AND NOT T54
R100 = 0R,_0402_2: CLABCONF0: = SB-SOM AND NOT T43 AND NOT T54
R112 = 0R,_0402_11: CLABCONF0: = SB-SOM AND NOT T54
R113 = 0R,_0402_4: CLABCONF0: = SB-SOM AND NOT T54
R1 R129 = 10K,1%,0402,1_16W_4: CLABCONF0: = SB-SOM
R133 = 0R,_0402_18: CLABCONF0: DNP
R134 = 0R,_0402_14: CLABCONF0: DNP
R135 = 0R,_0402_22: CLABCONF0: DNP
R138 = 0R,_0402_27: CLABCONF0: DNP
R139 = 0R,_0402_8: CLABCONF0: = SB-SOM
R140 = 0R,_0402_25: CLABCONF0: = SB-SOM
R39 R142 R151 = 0R,_0402_6: CLABCONF0: = SB-SOM
R152 = 0R,_0402_24: CLABCONF0: = SB-SOM
R153 = 0R,_0402_16: CLABCONF0: = SB-SOM
R174 = 0R,_0402_3: CLABCONF0: = SB-SOM
R175 = 0R,_0402_21: CLABCONF0: = SB-SOM
R2 R176 = 0R,_0402: CLABCONF0: = SB-SOM
R177 = 0R,_0402_23: CLABCONF0: = SB-SOM
R178 = 0R,_0402_15: CLABCONF0: = SB-SOM
R179 R328 = 0R,_0402_1: CLABCONF0: = SB-SOM
R180 = 0R,_0402_17: CLABCONF0: = SB-SOM
R192 = 0R,_0402_32: CLABCONF0: = SB-SOM
R193 = 0R,_0402_12: CLABCONF0: = SB-SOM
R194 = 0R,_0402_31: CLABCONF0: = SB-SOM
R195 = 0R,_0402_9: CLABCONF0: = SB-SOM
R196 = 0R,_0402_26: CLABCONF0: = SB-SOM
R36 R197 = 0R,_0402_7: CLABCONF0: = SB-SOM
R198 = 0R,_0402_5: CLABCONF0: = SB-SOM
R200 = 47K,_0402_3: CLABCONF0: = SB-SOM; P/N: 161C68001S
R201 = 47K,_0402_1: CLABCONF0: = SB-SOM; P/N: 161C68001S
R208 = 10K,1%,0402,1_16W_6: CLABCONF0: = SB-SOM AND NOT T54
R217 = 0R,_0402_13: CLABCONF0: = SB-SOM AND NOT T43 AND NOT QS600
R219 = 0R,_0402_10: CLABCONF0: = SB-SOM
R223 = 10K,1%,0402,1_16W_1: CLABCONF0: DNP
R224 = 0R,_0402_30: CLABCONF0: DNP
R225 = 0R,_0402_29: CLABCONF0: DNP
R226 = 0R,_0402_19: CLABCONF0: DNP
R227 = 10K,1%,0402,1_16W_5: CLABCONF0: = SB-SOM
R228 = 0R,_0402_28: CLABCONF0: = SB-SOM AND NOT T43 AND NOT QS600
RN1 RN3 RN16 RN17 RN19 = RN,10K,8P4R@0805: CLABCONF0: = SB-SOM
RN4 = RN,8.2K,10P8R@1206: CLABCONF0: DNP
S1-S4 = MISC_SHORT_NL: CLABCONF0: DNP
U3 U7 = TXS0102_0: CLABCONF0: = SB-SOM; P/N: 116A01020S
U4 = CP2104_0: CLABCONF0: = SB-SOM; P/N: 116A00140S
U5 U9 U10 = IP4220CZ6_0: CLABCONF0: = SB-SOM
U6 = MAX3243E_RS-232_3T5R_BGA: CLABCONF0: = SB-SOM
U8 = 24C02,_serial_EE,_2KB,_I2C: CLABCONF0: = SB-SOM
U30 = PCA9555: CLABCONF0: = SB-SOM
C48 = 22uF,6.3V,X5R: CLABCONF0: = SB-SOM AND NOT T43; P/N: 151B22610S
C49 = 100nF,_10V,_X7R,_10%,_0402: CLABCONF0: = SB-SOM AND NOT T43; Group: LAN2
C363 = 100nF,_10V,_X7R,_10%,_0402_1: CLABCONF0: = SB-SOM; Group: CAN
D1 = BAT54WS_0: CLABCONF0: = SB-SOM AND NOT T43
E5 E6 = HDR_1x3_100MIL_TH_JUMPER: CLABCONF0: = SB-SOM
F7 = Fuse,_0.75A_Ih,_1.5A_It: CLABCONF0: = SB-SOM AND NOT T43
J4 = HDMI_Connector: CLABCONF0: = SB-SOM AND NOT T43
L18-L20 L22 L23 L25 L26 L28 L30 = ESD_CHOKE_DIFFx2_10: CLABCONF0: = SB-SOM AND NOT T43; P/N: 142D11801S
L33-L37 = ESD_CHOKE_DIFFx2_10: CLABCONF0: = SB-SOM AND NOT T54 AND NOT QS600; P/N: 142D11801S
P11 = HDR_2x12_100MIL: CLABCONF0: = SB-SOM
Q6 Q7 = MOSFET_N_DUAL_0_0.4A_20V: CLABCONF0: = SB-SOM AND NOT T43
Q8 = N-MOSFET,NDS335N,100mOhm@2.5V: CLABCONF0: = SB-SOM AND NOT T43
R6 = 1K,1%,0402,1_16W: CLABCONF0: = SB-SOM; Group: CAN
R9 = 100K,_0402: CLABCONF0: = SB-SOM; P/N: 161C10031S
RN5-RN7 = RN,10K,8P4R@0805: CLABCONF0: = SB-SOM AND NOT T43
RN31 RN42-RN44 = RN,0R,8P4R@0805: CLABCONF0: = SB-SOM AND NOT T43
U13 = IP4220CZ6_0: CLABCONF0: = SB-SOM AND NOT T43
U34 = AduM1201: CLABCONF0: = SB-SOM; Group: CAN
U35 = TJA1050T: CLABCONF0: = SB-SOM; Group: CAN
C13 = 10uF,6.3V,0603,X5R: CLABCONF0: = SB-SOM
C14 = 10uF,6.3V,0603,X5R_1: CLABCONF0: = SB-SOM
C15 = 10uF,6.3V,0603,X5R_2: CLABCONF0: = SB-SOM
C16 = Cap_1uF,X5R,6.3V,0402: CLABCONF0: = SB-SOM
C22 = 10pF,50V,NPO,_5%,_0402_1: CLABCONF0: DNP
C23 = 10pF,50V,NPO,_5%,_0402: CLABCONF0: DNP
C177-C180 = 10uF,6_0.3V,0603,20%X5R: CLABCONF0: = SB-SOM
C185 = 100nF,_10V,_X7R,_10%,_0402_7: CLABCONF0: = SB-SOM; Group: LAN2
C183 C186 = 100nF,_10V,_X7R,_10%,_0402_1: CLABCONF0: = SB-SOM; Group: LAN2
C197 = 10uF,6_0.3V,0603,20%X5R: CLABCONF0: DNP
E1 E7 = HDR_1x2_100MIL_TH_JUMPER: CLABCONF0: = SB-SOM
F1 = Fuse,_0.75A_Ih,_1.5A_It: CLABCONF0: = SB-SOM; P/N: 175P22200S
F2 F3 F5 F6 = Fuse,_0.75A_Ih,_1.5A_It: CLABCONF0: = SB-SOM
FB1 = Ferrite_bead_,_120_Ohm@3A_2: CLABCONF0: DNP
FB2 = Ferrite_bead_,_120_Ohm@3A_1: CLABCONF0: = SB-SOM
L2-L7 L24 L32 = ESD_CHOKE_DIFFx2_10: CLABCONF0: = SB-SOM; P/N: 142D11801S
P3 = USB3_OTGMINIB_5: CLABCONF0: = SB-SOM; P/N: 180K01000S
P4 P5 P18 = HDR_2x17_100MIL_SMT: CLABCONF0: = SB-SOM
P6 = USB_A-TYPE_DOUBLE_TH: CLABCONF0: = SB-SOM; Group: Front Panel
P26 = USB_Conn.,_Fem,_Type_A_,_TH,_RA: CLABCONF0: = SB-SOM
Q2 Q3 Q15 = P-MOSFET,3A,20V,110mOhm@-1.8V: CLABCONF0: = SB-SOM
Q4 = N-MOSFET,NDS335N,100mOhm@2.5V: CLABCONF0: = SB-SOM
R3 = 100K,_0402_1: CLABCONF0: = SB-SOM; P/N: 161C10031S
R4 = 100K,_0402_2: CLABCONF0: = SB-SOM; P/N: 161C10031S
R7 = 100K,_0402: CLABCONF0: DNP; P/N: 161C10031S
R8 = 10K,1%,0402,1_16W: CLABCONF0: DNP
R10 = 0R,_0402_7: CLABCONF0: DNP
R11 = 10K,1%,0402,1_16W_5: CLABCONF0: DNP
R12 = 10K,1%,0402,1_16W_7: CLABCONF0: DNP
R13 = 10K,1%,0402,1_16W_1: CLABCONF0: = SB-SOM
R14 = 10K,1%,0402,1_16W_6: CLABCONF0: = SB-SOM
R15 = 649R,1%,0402,1_16W: CLABCONF0: = SB-SOM
R16 = 10K,1%,0402,1_16W_3: CLABCONF0: DNP
R111 = 0R,_0402_11: CLABCONF0: = SB-SOM AND NOT T43 AND NOT QS600
R137 = 0R,_0402_8: CLABCONF0: DNP
R141 = 0R,_0402: CLABCONF0: DNP
R31 R143 = 0R,_0402_3: CLABCONF0: DNP
R147 = 0R,_0402_13: CLABCONF0: = SB-SOM AND NOT QS600
R182 = 0R,_0402_1: CLABCONF0: = SB-SOM AND NOT QS600
R187 = 0R,_0402_12: CLABCONF0: = SB-SOM AND NOT QS600
R92 R188 = 0R,_0402_5: CLABCONF0: = SB-SOM AND NOT QS600
R189 = 0R,_0402_9: CLABCONF0: = SB-SOM AND NOT QS600
R38 R209 = 0R,_0402_2: CLABCONF0: DNP
R210 = 0R,_0402_10: CLABCONF0: DNP
R42 R211 = 0R,_0402_4: CLABCONF0: DNP
RN2 = RN,10K,8P4R@0805: CLABCONF0: DNP
RN18 = RN,10K,8P4R@0805: CLABCONF0: = SB-SOM; P/N: 163K04104S
RN41 = RN,0R,8P4R@0805: CLABCONF0: = SB-SOM AND NOT QS600 AND NOT T43
RN37-RN40 RN45 = RN,0R,8P4R@0805: CLABCONF0: = SB-SOM
U1 = TMP_164704: CLABCONF0: = SB-SOM
U2 = TMP_0: CLABCONF0: = SB-SOM
U33 = USB2_0.0_mux: CLABCONF0: = SB-SOM; P/N: 116A72220S
X1 = TMP_1: CLABCONF0: = SB-SOM; P/N: 141B12604I
C73 = Cap.,10uF,6.3V,0603,X5R_1: CLABCONF0: = SB-SOM
C74 = 100nF,_10V,_X7R,_10%,_0402_2: CLABCONF0: = SB-SOM; Group: LAN2
C75 = Cap.,10uF,6.3V,0603,X5R: CLABCONF0: = SB-SOM AND NOT T54 AND NOT QS600
C76 = 100nF,_10V,_X7R,_10%,_0402_7: CLABCONF0: = SB-SOM AND NOT T54 AND NOT QS600; Group: LAN2
C79 = 100nF,_10V,_X7R,_10%,_0402_3: CLABCONF0: = SB-SOM; Group: LAN2
C80 = 100nF,_10V,_X7R,_10%,_0402: CLABCONF0: = SB-SOM AND NOT T54 AND NOT QS600; Group: LAN2
C83 = 470pF,_50V,_X7R,_10%,_0603_1: CLABCONF0: DNP
C84 = 470pF,_50V,_X7R,_10%,_0603: CLABCONF0: DNP
C181 = 100nF,_10V,_X7R,_10%,_0402_5: CLABCONF0: = SB-SOM; Group: LAN2
C182 = 100nF,_10V,_X7R,_10%,_0402_4: CLABCONF0: = SB-SOM; Group: LAN2
C184 = 100nF,_10V,_X7R,_10%,_0402_6: CLABCONF0: = SB-SOM; Group: LAN2
D5 = BAT54C: CLABCONF0: = SB-SOM AND NOT T54 AND NOT QS600
D11 = BAT54A: CLABCONF0: = SB-SOM AND NOT T43; P/N: 130E05403S
P15 = FPC_40_4: CLABCONF0: = SB-SOM
P21 = Con.,1GBit_RJ45,_short: CLABCONF0: = SB-SOM
P22 = Con.,1GBit_RJ45,_short: CLABCONF0: = SB-SOM AND NOT T54 AND NOT QS600
R32 = 0R,_0402_1: CLABCONF0: DNP
R33 = 475R_1%,_0402_3: CLABCONF0: = SB-SOM AND NOT T54 AND NOT QS600
R34 = 475R_1%,_0402_2: CLABCONF0: = SB-SOM AND NOT T54 AND NOT QS600
R80 = 475R_1%,_0402: CLABCONF0: = SB-SOM AND NOT T43
R82 = 475R_1%,_0402_1: CLABCONF0: = SB-SOM AND NOT T43
R84 = 0R,_0402: CLABCONF0: = SB-SOM AND NOT T43
R116 = 0R,_0402_8: CLABCONF0: = SB-SOM AND NOT QS600
RN33-RN36 = RN,0R,8P4R@0805: CLABCONF0: DNP
SW1-SW3 = TACT_SW_6x6mm_SMT: CLABCONF0: = SB-SOM

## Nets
3V3_DBGUART232_RXD: U6.18(R1OUT) U7.1(B2)
3V3_DBGUART232_TXD: U6.12(T1IN) U7.8(B1)
3V3_DBGUARTUSB_RXD: U3.1(B2) U4.20(RXD)
3V3_DBGUARTUSB_TXD: U3.8(B1) U4.21(TXD)
AGND: C38.1 J1.1(COM) J2.1(COM) J3.1(COM) R21.2 ; also on sheet 10
GND: C13.1 C14.1 C15.1 C16.1 C17.1 C18.1 C19.1 C20.1 C21.1 C22.1 C23.1 C24.2 C25.2 C26.2 C27.2 C28.2 C29.2 C30.2 C31.2 C34.2 C35.2 C36.2 C39.1 C40.2 C41.2 C42.2 C43.2 C44.2 C45.2 C48.2 C49.2 C73.2 C74.2 C75.2 C76.2 C79.1 C80.2 C83.2 C84.2 C177.2 C178.2 C179.1 C180.1 C181.1 C182.1 C183.1 C184.1 C185.1 C186.1 C187.2 C188.2 C193.2 C195.1 C197.1 C363.2 E2.2 E3.2 E7.1 FB1.1 FB2.1 FB5.1 J4.2(D2_Shield) J4.5(D1_Shield) J4.8(D0_Shield) J4.11(CK_Shield) J4.17(GND) L2.5(GND) L2.6(GND) L3.5(GND) L3.6(GND) L4.5(GND) L4.6(GND) L5.5(GND) L5.6(GND) L6.5(GND) L6.6(GND) L7.5(GND) L7.6(GND) L18.5(GND) L18.6(GND) L19.5(GND) L19.6(GND) L20.5(GND) L20.6(GND) L22.5(GND) L22.6(GND) L23.5(GND) L23.6(GND) L24.5(GND) L24.6(GND) L25.5(GND) L25.6(GND) L26.5(GND) L26.6(GND) L28.5(GND) L28.6(GND) L30.5(GND) L30.6(GND) L32.5(GND) L32.6(GND) L33.5(GND) L33.6(GND) L34.5(GND) L34.6(GND) L35.5(GND) L35.6(GND) L36.5(GND) L36.6(GND) L37.5(GND) L37.6(GND) P5.25 P5.33 P8.8 P9.3(VSS1) P9.6(VSS2) P9.10(GND) P9.13(GND) P9.14(GND) P9.15(GND) P11.5 P11.6 P11.9 P11.10 P11.13 P11.14 P11.17 P11.18 P11.21 P11.22 P15.10(GND) P15.11(GND) P15.23(GND) P15.25(GND) P15.27(GND) P15.29(GND) P15.31(GN~{D}) P18.33 P18.34 P26.4(GND) Q5.1(S1) Q5.4(S2) Q7.1(S1) Q7.4(S2) Q16.1(S1) Q16.4(S2) Q18.1(S1) Q18.4(S2) R1.1 R7.2 R8.2 R11.2 R15.1 R16.2 R22.1 R33.2 R34.2 R328.1 RN3.3(RC1) RN6.5(RD2) RN16.1(RA1) RN16.2(RB1) RN16.3(RC1) RN16.4(RD1) RN17.2(RB1) RN17.3(RC1) RN17.4(RD1) RN18.3(RC1) RN18.4(RD1) S1.1 S2.1 S4.1 SW1.1 SW1.3 SW2.1 SW2.3 U1.6(GND) U2.29(P) U3.2(GND) U4.2(GND) U5.2(GND) U6.2(R2IN) U6.3(R3IN) U6.4(R4IN) U6.5(R5IN) U6.10(T3IN) U6.11(T2IN) U6.24(GND) U6.33(EPAD) U7.2(GND) U8.4(GND) U9.2(GND) U10.2(GND) U13.2(GND) U30.9(VSS) U33.4(GND) U33.8(\\~{O}E) U34.4(GND1) X1.2(Y2) X1.4(Y4) ; also on sheet 7 8 9 10 11 12 13 14
VBUS0: F1.2 R142.2 ; also on sheet 9 10 11 13 14
VBUS0_EN_3V3: R137.1 RN18.6(RC2) U1.1(EN_A) ; also on sheet 13
VBUS0_FUSED: C178.1 F1.1 P3.1(5VUSB)
VBUS0_nOVC_OD: RN18.8(RA2) U1.2(FLG_A)
VBUS0_S: R142.1 U1.8(OUT_A)
VBUS1: Q3.2(S) Q15.2(S) R143.1 U1.5(OUT_B) ; also on sheet 13
VBUS1_CON: C177.1 P26.1(VBUS) Q15.3(D) R209.1 RN19.6(RC2)
VBUS1_CON_nEN: E7.2 Q15.1(G) Q16.5(G2) RN19.1(RA1)
VBUS1_EN_3V3: R141.1 R147.2 RN18.5(RD2) U1.4(EN_B) ; also on sheet 14
VBUS1_HUB: C186.2 Q3.3(D) R12.1 R210.1 U2.27(VCC)
VBUS1_HUB_nEN: Q3.1(G) Q16.3(D2) R211.1 RN19.2(RB1)
VBUS1_nOVC_OD: R111.2 RN18.7(RB2) U1.3(FLG_B)
VCC_AUX1: P18.25 ; also on sheet 9
VCC_AUX2: P18.22 ; also on sheet 9
VCC_CM: R200.1 R201.2 R223.1 R227.2 ; also on sheet 9 10 12 14
VCC_USB_1: C180.2 F5.1 P6.1(VBUS)
VCC_USB_2: C179.2 F6.1 P6.5(VBUS)
100MIL_MFUNC_PCAM_DAT0/100DIFF_5N: P18.3 RN40.1(RA1)
100MIL_MFUNC_PCAM_DAT1/100DIFF_5P: P18.4 RN40.2(RB1)
100MIL_MFUNC_PCAM_DAT2/100DIFF_3N: P18.5 RN37.1(RA1)
100MIL_MFUNC_PCAM_DAT3/100DIFF_3P: P18.6 RN37.2(RB1)
100MIL_MFUNC_PCAM_DAT4/100DIFF_1P: P18.7 RN38.2(RB1)
100MIL_MFUNC_PCAM_DAT5/100DIFF_1N: P18.8 RN38.1(RA1)
100MIL_MFUNC_PCAM_DAT6/100DIFF_2P: P18.9 RN38.4(RD1)
100MIL_MFUNC_PCAM_DAT7/100DIFF_2N: P18.10 RN38.3(RC1)
100MIL_MFUNC_PCAM_DAT8/100DIFF_6N: P18.11 RN40.3(RC1)
100MIL_MFUNC_PCAM_DAT9/100DIFF_6P: P18.12 RN40.4(RD1)
100MIL_MFUNC_PCAM_DAT10: P18.13 ; also on sheet 12
100MIL_MFUNC_PCAM_DAT11: P18.14 ; also on sheet 12
100MIL_MFUNC_PCAM_DAT12: P18.15 ; also on sheet 12
100MIL_MFUNC_PCAM_DAT13: P18.16 ; also on sheet 12
100MIL_MFUNC_PCAM_DAT14: P18.17 ; also on sheet 12
100MIL_MFUNC_PCAM_DAT15: P18.18 ; also on sheet 12
100MIL_MFUNC_PCAM_DATA_EN: P18.28 R42.1
100MIL_MFUNC_PCAM_HSYNC/100DIFF_7N: P18.32 RN39.1(RA1)
100MIL_MFUNC_PCAM_PCLK/100DIFF_4N: P18.26 RN37.4(RD1)
100MIL_MFUNC_PCAM_RESET: P18.29 RN39.4(RD1)
100MIL_MFUNC_PCAM_SHUTTER: P18.24 RN39.3(RC1)
100MIL_MFUNC_PCAM_VSYNC/100DIFF_7P: P18.31 RN39.2(RB1)
100MIL_MFUNC_PCAM_WEN/100DIFF_4P: P18.30 R42.2 RN37.3(RC1)
ADDN_mPCIE_USB_DN: L4.3 ; also on sheet 8
ADDN_mPCIE_USB_DP: L4.4 ; also on sheet 8
ALT_BOOT_ACT: E1.2 R92.1 SW3.1 SW3.3 ; also on sheet 10 14
AMPR: C37.2 R20.1
BOOST_5V: C48.1 C49.1 C181.2 C182.2 C187.1 C195.2 E5.3 F2.2 F3.2 F7.2 FB3.1 P15.4(VCC_HIGH) P15.13(VCC_HIGH) P18.1 Q2.2(S) R2.1 R14.2 R143.2 R209.2 R210.2 RN19.7(RB2) RN19.8(RA2) U1.7(VCC) ; also on sheet 7 8 9
CAN_GND: P5.34 R6.1 R328.2 U34.5(GND2) U35.2(GND)
CAN_H: P5.30 U35.7(CANH)
CAN_L: P5.32 U35.6(CANL)
CAN_RX_3V3: U34.2(OUTA) ; also on sheet 13
CAN_STB_PD: R6.2 U35.8(S)
CAN_TX_3V3: R9.2 U34.3(INB) ; also on sheet 13
CAN_VCC: P5.28 R2.2 U34.8(VCC2) U35.3(VCC)
CARRIER_3V3_GPIO0_0: R138.2 U30.1(I/O0.0)
CARRIER_3V3_GPIO0_1: R139.2 U30.2(I/O0.1)
CARRIER_3V3_GPIO0_2: R140.2 U30.3(I/O0.2)
CARRIER_3V3_GPIO0_3: R174.2 U30.4(I/O0.3)
CARRIER_3V3_GPIO0_4: R175.2 U30.5(I/O0.4)
CARRIER_3V3_GPIO0_5: R176.2 U30.6(I/O0.5)
CARRIER_3V3_GPIO0_6: R177.2 U30.7(I/O0.6)
CARRIER_3V3_GPIO0_7: R180.2 U30.8(I/O0.7)
CARRIER_3V3_GPIO1_0: R178.2 U30.10(I/O1.0)
CARRIER_3V3_GPIO1_1: R179.2 U30.11(I/O1.1)
CARRIER_3V3_GPIO1_2: R198.2 U30.12(I/O1.2)
CARRIER_3V3_GPIO1_3: R219.2 U30.13(I/O1.3)
CARRIER_3V3_GPIO1_5: R151.2 U30.15(I/O1.5)
CARRIER_3V3_GPIO1_6: R152.2 U30.16(I/O1.6)
CARRIER_3V3_GPIO1_7: R153.2 U30.17(I/O1.7)
CARRIER_EEPROM_WP: E4.1 R22.2 U8.7(WP)
CARRIER_I2C_SCL_3V3: P11.23 Q1.6(D1) RN1.3(RC1) U30.19(SCL) ; also on sheet 7 8 12
CARRIER_I2C_SCL_VPER: P15.5(I2C_SCK) Q1.1(S1) RN1.2(RB1) U8.6(SCL) ; also on sheet 9 11 13 14
CARRIER_I2C_SDA_3V3: P11.24 Q1.3(D2) RN1.4(RD1) U30.20(SDA) ; also on sheet 7 8 12
CARRIER_I2C_SDA_VPER: P15.3(I2C_SDA) Q1.4(S2) RN1.1(RA1) U8.5(SDA) ; also on sheet 9 11 13 14
CHASSIS: J4.20(SHELL1) J4.21(SHELL2) P3.NC1(CHASSIS) P3.NC2(CHASSIS) P3.NC3(CHASSIS) P3.NC4(CHASSIS) P3.NC5(CHASSIS) P3.NC6(CHASSIS) P6.9(SHIELD) P6.10(SHIELD) P6.11(SHIELD) P6.12(SHIELD) P7.6(SHIELD1) P7.7(SHIELD2) P7.8(SHIELD3) P7.9(SHIELD4) P8.9(CHASSIS) P8.10(CHASSIS) P8.11(CHASSIS) P8.12(CHASSIS) P21.S1(SHIELD) P21.S2(SHIELD) P22.S1(SHIELD) P22.S2(SHIELD) P26.5(SHELL_1) P26.6(SHELL_2) ; also on sheet 7 8 10
CM_EEPROM_WP: E2.1 R116.2
COM_VBUSP2_5V: C14.2 F3.1 P5.27
COM_VBUSP3_5V: C13.2 F2.1 P5.19
CP2104VPP: C29.1 U4.16(VPP)
DEBUGSEL: E3.1 Q5.2(G1) Q18.5(G2) R208.2 R223.2 RN3.6(RC2)
DVI_EN_3V3: R151.1 ; also on sheet 7
EPR_A0: R224.2 RN16.8(RA2) U8.1(A0)
EPR_A1: R225.2 RN16.7(RB2) U8.2(A1)
EPR_A2: R226.2 RN16.6(RC2) U8.3(A2)
ETH1_CT1: C73.1 C74.1 P21.P5(CT) R31.1
ETH1_CT2: C79.2 P21.P6(CT)
ETH1_GREEN_LED_AN: P21.P12(LED1_A) R80.1 ; also on sheet 13
ETH1_GREEN_LED_CAT: D11.3(CATHODE) P21.P11(LED1_C) ; also on sheet 13
ETH1_YELLOW_LED_AN: P21.P14(LED2_A) R82.1 ; also on sheet 13
ETH1_YELLOW_LED_CAT: P21.P13(LED2_C) R84.1 ; also on sheet 13
ETH2_CT1: C75.1 C76.1 P22.P5(CT) R32.1
ETH2_CT2: C80.1 P22.P6(CT)
ETH2_GREEN_LED_AN: C83.1 D5.3(CATHODE) P22.P12(LED1_A)
ETH2_GREEN_LED_CAT: P22.P11(LED1_C) R33.1
ETH2_LED_LINK10_100: D5.1(ANODE1) ; also on sheet 13
ETH2_LINK-LED_1000: D5.2(ANODE2) ; also on sheet 13
ETH2_LINK-LED_ACT: C84.1 P22.P14(LED2_A) ; also on sheet 13
ETH2_MDI0N: P22.P2(MDI0-) ; also on sheet 13
ETH2_MDI0P: P22.P1(MDI0+) ; also on sheet 13
ETH2_MDI1N: P22.P4(MDI1-) ; also on sheet 13
ETH2_MDI1P: P22.P3(MDI1+) ; also on sheet 13
ETH2_MDI2N: P22.P8(MDI2-) ; also on sheet 13
ETH2_MDI2P: P22.P7(MDI2+) ; also on sheet 13
ETH2_MDI3N: P22.P10(MDI3-) ; also on sheet 13
ETH2_MDI3P: P22.P9(MDI3+) ; also on sheet 13
ETH2_YELLOW_LED_CAT: P22.P13(LED2_C) R34.1
EXPANDER_A0: R134.1 RN17.5(RD2) U30.18(A0)
EXPANDER_A1: R135.1 RN17.6(RC2) U30.23(A1)
EXPANDER_A2: R133.1 RN17.7(RB2) U30.24(A2)
EXPANDER_nINT: R78.2 R129.1 U30.22(\\~{IN}T) ; also on sheet 14
GPLED_CAT: R219.1 ; also on sheet 10
HDMI_5V: D1.CATHODE J4.18(+5V) RN5.7(RB2) RN5.8(RA2) RN7.8(RA2) U13.5(VBUS)
HDMI_5V_D: D1.ANODE F7.1
HDMI_CEC_5V: J4.13(CE_Remote) Q8.3(D) RN7.1(RA1) U13.3(IO2)
HDMI_CEC_VPER: Q8.2(S) RN7.4(RD1) RN31.8(RA2)
HDMI_DDC_SCL: J4.15(DDC_CLK) Q6.3(D2) RN5.1(RA1) U13.6(IO4)
HDMI_DDC_SCL_VPER: Q6.4(S2) RN5.4(RD1) RN31.6(RC2)
HDMI_DDC_SDA: J4.16(DDC_DATA) Q6.6(D1) RN5.2(RB1) U13.4(IO3)
HDMI_DDC_SDA_VPER: Q6.1(S1) RN5.3(RC1) RN31.5(RD2)
HDMI_HOTPLUG: J4.19(HP_DET) Q7.2(G1) RN6.4(RD1) U13.1(IO1)
HDMI_HTPLGVPER: Q7.3(D2) RN6.3(RC1) RN31.7(RB2)
HDMI_nHOTPLUG: Q7.5(G2) Q7.6(D1) RN6.1(RA1)
HDMI_TXD0N: L19.3 RN43.7(RB2)
HDMI_TXD0N_CON: J4.9(D0-) L19.2
HDMI_TXD0P: L19.4 RN43.8(RA2)
HDMI_TXD0P_CON: J4.7(D0+) L19.1
HDMI_TXD1N: L22.3 RN42.5(RD2)
HDMI_TXD1N_CON: J4.6(D1-) L22.2
HDMI_TXD1P: L22.4 RN42.6(RC2)
HDMI_TXD1P_CON: J4.4(D1+) L22.1
HDMI_TXD2N: L25.3 RN42.7(RB2)
HDMI_TXD2N_CON: J4.3(D2-) L25.2
HDMI_TXD2P: L25.4 RN42.8(RA2)
HDMI_TXD2P_CON: J4.1(D2+) L25.1
HDMI_TXDCN: L18.3 RN43.5(RD2)
HDMI_TXDCN_CON: J4.12(CK-) L18.2
HDMI_TXDCP: L18.4 RN43.6(RC2)
HDMI_TXDCP_CON: J4.10(CK+) L18.1
HDR_HSUSB2_DN: P5.29 R188.2
HDR_HSUSB2_DP: P5.31 R189.2
HSUSB_GND: FB2.2 P6.4(GND) P6.8(GND) S2.2
HUB_UP_DN: U2.1(UD-) U33.6(HSD2-)
HUB_UP_DP: U2.2(UD+) U33.2(HSD2+)
HUBTEST: R11.1 U2.18(TEST)
HUBUSB1_DN: L6.3 U2.3(DD-1)
HUBUSB1_DP: L6.4 U2.4(DD+1)
HUBUSB2_DN: L7.3 U2.6(DD-2)
HUBUSB2_DP: L7.4 U2.7(DD+2)
HUBUSB3_DN: L5.1 U2.12(DD-3)
HUBUSB3_DP: L5.2 U2.13(DD+3)
HUBUSB4_DN: L4.2 U2.15(DD-4)
HUBUSB4_DP: L4.1 U2.16(DD+4)
LCD_nSTANDBY_3V3: R152.1 ; also on sheet 7
LVDS_CLKN: L30.3 L34.2 P11.20
LVDS_CLKP: L30.4 L34.1 P11.19
LVDS_EN_3V3: R153.1 ; also on sheet 7
LVDS_N0: L28.3 L36.2 P11.4
LVDS_N1: L26.3 L35.2 P11.8
LVDS_N2: L23.3 L37.2 P11.12
LVDS_N3: L20.3 L33.2 P11.16
LVDS_P0: L28.4 L36.1 P11.3
LVDS_P1: L26.4 L35.1 P11.7
LVDS_P2: L23.4 L37.1 P11.11
LVDS_P3: L20.4 L33.1 P11.15
MAIN_PWR_CYCLE: R198.1 ; also on sheet 12
MFUNC_P1-21: P5.26 ; also on sheet 13
MFUNC_P1-23: P5.24 ; also on sheet 13
MFUNC_P1-27: P5.22 ; also on sheet 13
MFUNC_P1-29: P5.20 ; also on sheet 13
MIC_IN: C37.1 C38.2 J2.2(L) R18.2 R21.1
mPCIE_USB_DN: L5.4 ; also on sheet 8
mPCIE_USB_DP: L5.3 ; also on sheet 8
MUX_DN: R182.2 U33.5(D-) ; also on sheet 14
MUX_DP: R187.2 U33.3(D+) ; also on sheet 14
MUX_EMI_USB_CON_DN: L24.4 P26.2(D-)
MUX_EMI_USB_CON_DP: L24.3 P26.3(D+)
MUX_USB_CON_DN: L24.1 U33.7(HSD1-)
MUX_USB_CON_DP: L24.2 U33.1(HSD1+)
nUSBSERIALEN: Q5.5(G2) Q5.6(D1) RN3.8(RA2) U7.6(OE)
OC#1_PU: RN2.8(RA2) U2.25(OVR#[1])
OC#2_PU: RN2.7(RB2) U2.24(OVR#[2])
OC#3_PU: RN2.6(RC2) U2.20(OVR#[3])
OC#4_PU: RN2.5(RD2) U2.19(OVR#[4])
OTG_DN: L2.2 P3.2(D-)
OTG_DP: L2.1 P3.3(D+)
P1-3_UART2_TX: RN44.2(RB1) ; also on sheet 10 13
P1-4_ETH_LED2_ACT: R84.2 ; also on sheet 10 13
P1-5_UART2_RX: RN44.1(RA1) ; also on sheet 10 13
P1-6_ETH_MDI0N: P21.P2(MDI0-) ; also on sheet 10
P1-7_UART2_CTS: P4.1 ; also on sheet 10 13
P1-8_ETH_MDI0P: P21.P1(MDI0+) ; also on sheet 10
P1-9_UART2_RTS: P4.3 ; also on sheet 10 13
P1-11_UART1_TX: P5.15 ; also on sheet 10
P1-12_ETH_MDI1N: P21.P4(MDI1-) ; also on sheet 10
P1-13_UART1_RX: P5.17 ; also on sheet 10
P1-14_ETH_MDI1P: P21.P3(MDI1+) ; also on sheet 10
P1-15_UART1_CTS: RN44.3(RC1) ; also on sheet 10 13
P1-16_ETH_LED1_SPD: D11.2(ANODE2) ; also on sheet 10 13
P1-17_UART1_RTS: RN44.4(RD1) ; also on sheet 10 13
P1-18_ETH_MDI2N: P21.P8(MDI2-) ; also on sheet 10
P1-20_ETH_MDI2P: P21.P7(MDI2+) ; also on sheet 10
P1-22_ETH_LED3: D11.1(ANODE1) ; also on sheet 10 13
P1-24_ETH_MDI3N: P21.P10(MDI3-) ; also on sheet 10
P1-25_TMDS_DDC_SCL: RN31.3(RC1) ; also on sheet 10
P1-26_ETH_MDI3P: P21.P9(MDI3+) ; also on sheet 10
P1-30_TMDS_CLKP: RN43.3(RC1) ; also on sheet 10 13
P1-31_TMDS_DDC_SDA: RN31.4(RD1) ; also on sheet 10
P1-32_TMDS_CLKN: RN43.4(RD1) ; also on sheet 10 13
P1-33_LVDS_CLKP: L30.1 ; also on sheet 10
P1-34_HDMI_CEC: RN31.1(RA1) ; also on sheet 10 13
P1-35_LVDS_CLKN: L30.2 ; also on sheet 10
P1-36_TMDS_D0P: RN43.1(RA1) ; also on sheet 10 13
P1-38_TMDS_D0N: RN43.2(RB1) ; also on sheet 10 13
P1-39_LVDS_P0: L28.1 ; also on sheet 10
P1-40_HDMI_HPD: RN31.2(RB1) ; also on sheet 10 13
P1-41_LVDS_N0: L28.2 ; also on sheet 10
P1-42_TMDS_D1P: RN42.3(RC1) ; also on sheet 10 13
P1-43_I2C2_SCL: P4.21 ; also on sheet 10 11
P1-44_TMDS_D1N: RN42.4(RD1) ; also on sheet 10 13
P1-45_LVDS_P1: L26.1 ; also on sheet 10
P1-47_LVDS_N1: L26.2 ; also on sheet 10
P1-48_TMDS_D2P: RN42.1(RA1) ; also on sheet 10 13
P1-49_I2C2_SDA: P4.23 ; also on sheet 10 11
P1-50_TMDS_D2N: RN42.2(RB1) ; also on sheet 10 13
P1-51_LVDS_P2: L23.1 ; also on sheet 10
P1-52_SPI_CS1: P4.12 ; also on sheet 10
P1-53_LVDS_N2: L23.2 ; also on sheet 10
P1-54_GPIO8: P4.14 ; also on sheet 10
P1-56_GPIO9: P4.16 ; also on sheet 10
P1-57_LVDS_P3: L20.1 ; also on sheet 10 13
P1-58_SPI_CS0: P4.18 ; also on sheet 10 14
P1-59_LVDS_N3: L20.2 ; also on sheet 10
P1-60_GPIO10: P4.20 R78.1 ; also on sheet 10
P1-61_MMC0_CD: P9.11(CD) R19.2 ; also on sheet 10
P1-62_GPIO11: P4.22 ; also on sheet 10
P1-63_SPI_SOMI: P4.2 ; also on sheet 10
P1-65_SPI_SIMO: P4.4 ; also on sheet 10
P1-66_RTOUCH_XP: P5.4 ; also on sheet 7 10
P1-67_MMC0_WP: P9.12(WP) R17.2 ; also on sheet 10
P1-68_RTOUCH_XN: P5.6 ; also on sheet 7 10
P1-69_SPI_CLK: P4.6 ; also on sheet 10 14
P1-70_RTOUCH_YP: P5.14 ; also on sheet 7 10
P1-72_RTOUCH_YN: P5.16 ; also on sheet 7 10
P1-75_GPIO3: P4.10 ; also on sheet 10
P1-77_PCAM_DAT4/100DIFF_1P: RN33.7(RB2) RN38.7(RB2) ; also on sheet 10
P1-79_PCAM_DAT5/100DIFF_1N: RN33.8(RA2) RN38.8(RA2) ; also on sheet 10
P1-80_MMC0_CLK: R196.2 ; also on sheet 10
P1-81_PCAM_SHUTTER: RN36.6(RC2) RN39.6(RC2) ; also on sheet 10
P1-82_MMC0_CMD: R197.2 ; also on sheet 10
P1-83_PCAM_DAT6/100DIFF_2P: RN33.5(RD2) RN38.5(RD2) ; also on sheet 10
P1-84_MMC0_DAT0: R195.2 ; also on sheet 10
P1-85_PCAM_DAT7/100DIFF_2N: RN33.6(RC2) RN38.6(RC2) ; also on sheet 10
P1-86_MMC0_DAT1: R194.2 ; also on sheet 10
P1-88_MMC0_DAT2: R193.2 ; also on sheet 10
P1-89_PCAM_DAT2/100DIFF_3N: RN34.8(RA2) RN37.8(RA2) ; also on sheet 10
P1-90_MMC0_DAT3: R192.2 ; also on sheet 10
P1-91_PCAM_DAT3/100DIFF_3P: RN34.7(RB2) RN37.7(RB2) ; also on sheet 10
P1-93_PCAM_STROBE: R36.1 ; also on sheet 10
P1-95_PCAM_PCLK/100DIFF_4N: RN34.5(RD2) RN37.5(RD2) ; also on sheet 10
P1-97_PCAM_WEN/100DIFF_4P: RN34.6(RC2) RN37.6(RC2) ; also on sheet 10
P1-99_PCAM_RESET: RN36.5(RD2) RN39.5(RD2) ; also on sheet 10
P1-101_PCAM_DAT0/100DIFF_5N: RN35.8(RA2) RN40.8(RA2) ; also on sheet 10
P1-103_PCAM_DAT1/100DIFF_5P: RN35.7(RB2) RN40.7(RB2) ; also on sheet 10
P1-107_PCAM_DAT8/100DIFF_6N: RN35.6(RC2) RN40.6(RC2) ; also on sheet 10
P1-109_PCAM_DAT9/100DIFF_6P: RN35.5(RD2) RN40.5(RD2) ; also on sheet 10
P1-111_UARTDBG_TX: R99.2 ; also on sheet 10 11
P1-113_PCAM_VSYNC/100DIFF_7P: RN36.7(RB2) RN39.7(RB2) ; also on sheet 10
P1-115_PCAM_HSYNC/100DIFF_7N: RN36.8(RA2) RN39.8(RA2) ; also on sheet 10
P1-117_UARTDBG_RX: R100.1 ; also on sheet 10 11
P1-137_I2S1_CLKX: P4.27 ; also on sheet 10
P1-139_I2S1_DOUT: P4.25 ; also on sheet 10
P1-143_I2S1_DIN: P4.5 ; also on sheet 10
P1-145_I2S1_FSX: P4.7 ; also on sheet 10
P1-147_SDIO_CMD: P4.9 ; also on sheet 10
P1-149_SDIO_DAT3: P4.11 ; also on sheet 10
P1-151_SDIO_DAT2: P4.13 ; also on sheet 10
P1-152_GPIO1: P5.13 ; also on sheet 9 10
P1-153_SDIO_DAT1: P4.15 ; also on sheet 10
P1-154_GPIO2: P4.8 ; also on sheet 10
P1-155_SDIO_DAT0: P4.17 ; also on sheet 10
P1-156_USBPWREN: R147.1 ; also on sheet 10
P1-157_SDIO_CLK: P4.19 ; also on sheet 10
P1-158_HSUSB3_DN: P5.21 ; also on sheet 10
P1-160_HSUSB3_DP: P5.23 ; also on sheet 10
P1-161_GPIO4: P5.8 ; also on sheet 10 11 14
P1-162_nOVC: R111.1 ; also on sheet 10
P1-163_GPIO5: P5.12 ; also on sheet 10 11
P1-164_HSUSB2_DN: R188.1 ; also on sheet 10 14
P1-165_PWRON: SW1.2 SW1.4 ; also on sheet 10
P1-166_HSUSB2_DP: R189.1 ; also on sheet 10 14
P1-167: RN45.8(RA2) ; also on sheet 10 12
P1-167_100MIL: P4.24 RN45.1(RA1)
P1-169: RN45.7(RB2) ; also on sheet 10 12
P1-169_100MIL: P4.26 RN45.2(RB1)
P1-170_HSUSB1_DN: R182.1 ; also on sheet 10
P1-171_COLD_RESET_IN: SW2.2 SW2.4 ; also on sheet 10
P1-172_HSUSB1_DP: R187.1 ; also on sheet 10
P1-173: RN45.6(RC2) ; also on sheet 10 12
P1-173_100MIL: P4.28 RN45.3(RC1)
P1-174_USBOTG_ID: P3.4(ID) ; also on sheet 10
P1-175: RN45.5(RD2) ; also on sheet 10 12
P1-175_100MIL: P4.30 RN45.4(RD1)
P1-176_USBOTG_DP: L2.4 ; also on sheet 10
P1-178_USBOTG_DN: L2.3 ; also on sheet 10
P1-179_RESERVED2: P5.2 ; also on sheet 10 14
P1-182_MFUNC: P5.9 ; also on sheet 12
P1-182_USBSS_RXP: RN41.1(RA1) ; also on sheet 10 12
P1-184_MFUNC: P5.7 ; also on sheet 12
P1-184_USBSS_RXN: RN41.2(RB1) ; also on sheet 10 12
P1-185_ALT_BOOT: E1.1 SW3.2 SW3.4 ; also on sheet 10 14
P1-187_nRESET_WARM: P5.10 ; also on sheet 10
P1-188_MFUNC: P5.3 ; also on sheet 12
P1-188_USBSS_TXP: RN41.3(RC1) ; also on sheet 10 12
P1-189_EEPROM_WP: R116.1 ; also on sheet 10
P1-190_MFUNC: P5.1 ; also on sheet 12
P1-190_USBSS_TXN: RN41.4(RD1) ; also on sheet 10 12
P1-191_MICBIAS: R18.1 ; also on sheet 10
P1-193_MICIN: R20.2 ; also on sheet 10
P1-194_GPIO6: P5.18 ; also on sheet 7 10
P1-197_RLINEIN: J3.3(R) ; also on sheet 10
P1-198_PER_PWREN_OUT: P4.29 ; also on sheet 10
P1-199_LLINEIN: J3.2(L) ; also on sheet 10
P1-201_RHPOUT: J1.3(R) ; also on sheet 10
P1-203_LHPOUT: J1.2(L) ; also on sheet 10
P26LED_AN: DS6.ANODE R214.2
PCIE0_nPERST_3V3: R139.1 ; also on sheet 8 12
PCIE1_nPERST_3V3: R140.1 ; also on sheet 8 12
PCIE_REFCLKSRC_nPWRDWN: R180.1 ; also on sheet 12
PCIE_REFCLKSRC_nSTOP: R177.1 ; also on sheet 12
PCIE_REFCLKSRC_OE0: R175.1 ; also on sheet 12
PCIE_REFCLKSRC_OE3: R176.1 ; also on sheet 12
PCIE_REFCLKSRC_OEINV: R174.1 ; also on sheet 12
PCIE_REFCLKSRC_PLL: R178.1 ; also on sheet 12
PCIE_REFCLKSRC_PLLBW: R179.1 ; also on sheet 12
PORTS_nPWR: Q2.1(G) Q4.3(D) R14.1
PORTS_nPWR_3V3: Q4.2(S) R3.2 U2.26(I2C_SDA)
RGB_LVDS_CLKN: L34.3 ; also on sheet 7
RGB_LVDS_CLKP: L34.4 ; also on sheet 7
RGB_LVDS_N0: L36.3 ; also on sheet 7
RGB_LVDS_N1: L35.3 ; also on sheet 7
RGB_LVDS_N2: L37.3 ; also on sheet 7
RGB_LVDS_N3: L33.3 ; also on sheet 7
RGB_LVDS_P0: L36.4 ; also on sheet 7
RGB_LVDS_P1: L35.4 ; also on sheet 7
RGB_LVDS_P2: L37.4 ; also on sheet 7
RGB_LVDS_P3: L33.4 ; also on sheet 7
RS232_RXD: R217.1 ; also on sheet 11
RS232_TXD: R228.1 ; also on sheet 11
RS232DB_LED: DS2.ANODE R200.2
RS232DB_LEDCAT: DS2.CATHODE Q18.6(D1)
RS232DB_RXD_CON: P8.3 R112.2 R217.2
RS232DB_TXD_CON: P8.1 R113.2 R228.2
RXD_OUTB: U34.6(OUTB) U35.1(TxD)
SB_RS232_RXD: R112.1 U6.1(R1IN)
SB_RS232_TXD: R113.1 U6.6(T1OUT)
SDCARD_CLK: P9.5(CLK) R196.1 RN4.7(R6) U10.4(IO3)
SDCARD_CMD: P9.2(CMD) R197.1 RN4.6(R5) U10.6(IO4)
SDCARD_DAT0: P9.7(DAT0) R195.1 RN4.4(R4) U9.6(IO4)
SDCARD_DAT1: P9.8(DAT1) R194.1 RN4.3(R3) U9.4(IO3)
SDCARD_DAT2: P9.9(DAT2) R193.1 RN4.2(R2) U9.3(IO2)
SDCARD_DAT3: P9.1(DAT3) R192.1 RN4.1(R1) U9.1(IO1)
SERIAL_USBGND: FB5.2 P7.5(GND) S4.2
SERIAL_VBUS: C28.1 FB4.1 R208.1 S3.1 U4.7(REGIN) U4.8(VBUS) U5.4(IO3)
SERIAL_VBUSIN: FB4.2 P7.1(VBUS) S3.2
SP_PMP_C1N: C33.2 U6.23(C1-)
SP_PMP_C1P: C33.1 U6.28(C1+)
SP_PMP_C2N: C32.2 U6.30(C2-)
SP_PMP_C2P: C32.1 U6.29(C2+)
SP_PMP_VN: C35.1 U6.31(V-)
SP_PMP_VP: C36.1 U6.27(V+)
SS_TXN: C118.2 L3.3
SS_TXP: C119.2 L3.4
TXD_INA: U34.7(INA) U35.4(RxD)
UART1_CTS: P4.34 RN44.6(RC2)
UART1_RTS: P4.32 RN44.5(RD2)
UART2_RX: P4.31 RN44.8(RA2)
UART2_TX: P4.33 RN44.7(RB2)
UARTDBG_RX: R100.2 U3.5(A1) U7.4(A2) ; also on sheet 13
UARTDBG_TX: R99.1 U3.4(A2) U7.5(A1) ; also on sheet 13
USB0_GND: FB1.2 P3.5(GND) P3.8(GNDD) S1.2
USB1N_C: L6.2 P6.2(D-)
USB1P_C: L6.1 P6.3(D+)
USB2N_C: L7.2 P6.6(D-)
USB2P_C: L7.1 P6.7(D+)
USB_GANG_PD: R4.2 R7.1 U2.23(GANG)
USB_HUB_nRESET_GPIO_3V3: C197.2 R12.2 R13.2 R16.1 R138.1 U2.17(RESET#)
USB_RREF: R15.2 U2.8(RREF)
USB_SELF_PWR: R5.2 R8.1 U2.22(SELFPWR)
USBDB_LED: DS3.ANODE R201.1
USBDB_LEDCAT: DS3.CATHODE Q18.2(G1) Q18.3(D2) R227.1
USBHUB_DOWNSTREAM_5V: F5.2 F6.2 FB3.2 Q2.3(D)
USBMUX_nSEL: Q16.2(G1) R1.2 R211.2 RN19.3(RC1)
USBMUX_SEL: DS6.CATHODE Q16.6(D1) RN19.4(RD1) U33.10(SEL)
USBSERIAL_3V45: C24.1 C25.1 C27.1 RN3.4(RD1) U3.7(VCCB) U4.5(VIO) U4.6(VDD)
USBSERIAL_DN: P7.2(D-) U4.4(DN) U5.6(IO4)
USBSERIAL_DP: P7.3(D+) U4.3(DP) U5.1(IO1)
USBSERIAL_nRST: RN3.5(RD2) U4.9(RST#)
USBSERIALEN: Q5.3(D2) RN3.7(RB2) U3.6(OE)
USBSS_RXN: L32.3 RN41.7(RB2)
USBSS_RXN_CON: L32.2 P3.9(RX-)
USBSS_RXP: L32.4 RN41.8(RA2)
USBSS_RXP_CON: L32.1 P3.10(RX+)
USBSS_TXN: C118.1 RN41.5(RD2)
USBSS_TXN_CON: L3.2 P3.6(TX-)
USBSS_TXP: C119.1 RN41.6(RC2)
USBSS_TXP_CON: L3.1 P3.7(TX+)
VA_LVDS: E6.2 P11.2
VB_LVDS: E5.2 P11.1
VCTAP: R31.2 R32.2 ; also on sheet 10
VIPADP_FIELD: P15.2(FIELD) R38.2
VIPADP_FLASH_STB: P15.1(FLASH_STB) R36.2
VIPADP_HSYNC: P15.9(HSYNC) RN36.1(RA1)
VIPADP_nRESET: P15.6(nRST) R35.2 R39.2
VIPADP_nRESET/VIPADP_FIELD: R38.1 R39.1 RN36.4(RD1)
VIPADP_PDATA0: P15.24(PDATA0) RN35.1(RA1)
VIPADP_PDATA1: P15.26(PDATA1) RN35.2(RB1)
VIPADP_PDATA2: P15.19(PDATA2) RN34.1(RA1)
VIPADP_PDATA3: P15.21(PDATA3) RN34.2(RB1)
VIPADP_PDATA4: P15.22(PDATA4) RN33.2(RB1)
VIPADP_PDATA5: P15.20(PDATA5) RN33.1(RA1)
VIPADP_PDATA6: P15.18(PDATA6) RN33.4(RD1)
VIPADP_PDATA7: P15.16(PDATA7) RN33.3(RC1)
VIPADP_PDATA8: P15.14(PDATA8) RN35.3(RC1)
VIPADP_PDATA9: P15.12(PDATA9) RN35.4(RD1)
VIPADP_PIXCLK: P15.28(PIX_CLK) RN34.4(RD1)
VIPADP_SHTR: P15.36(SHTR) RN36.3(RC1)
VIPADP_VSYNC: P15.7(VSYNC) RN36.2(RB1)
VIPADP_WE: P15.32(WE) RN34.3(RC1)
VSB_3V3: C30.1 C34.1 C40.1 C41.1 C42.1 C43.1 C44.1 C45.1 C185.2 C193.1 C363.1 E5.1 E6.3 P5.11 P9.4(VDD) R9.1 R10.2 R80.2 R82.2 R133.2 R134.2 R135.2 R137.2 R141.2 R214.1 RN1.5(RD2) RN1.6(RC2) RN4.5(COM1) RN4.10(COM2) RN6.8(RA2) RN18.1(RA1) RN18.2(RB1) RN19.5(RD2) U6.21(FORCEOFF) U6.22(FORCEON) U6.26(VCC3) U7.7(VCCB) U9.5(VBUS) U10.5(VBUS) U30.21(VDD) U33.9(VCC) U34.1(VCC1) ; also on sheet 7 8 9 10 12
VSB_PER: C26.1 C31.1 C39.2 C183.2 C184.2 C188.1 E4.2 E6.1 P5.5 P15.15(VCC_IO) P15.17(VCC_IO) P18.2 Q1.2(G1) Q1.5(G2) Q6.2(G1) Q6.5(G2) Q8.1(G) R17.1 R19.1 R35.1 R92.2 R129.2 R224.1 R225.1 R226.1 RN1.7(RB2) RN1.8(RA2) RN3.1(RA1) RN3.2(RB1) RN5.5(RD2) RN5.6(RC2) RN6.6(RC2) RN7.5(RD2) U3.3(VCCA) U7.3(VCCA) U8.8(VCC) ; also on sheet 7 9 10 14
VUSB_3V3: C15.2 C16.2 C17.2 C18.2 C19.2 C20.2 C21.2 Q4.1(G) R3.1 R4.1 R5.1 R10.1 R13.1 RN2.1(RA1) RN2.2(RB1) RN2.3(RC1) RN2.4(RD1) U2.5(VCCA) U2.9(VCCA) U2.14(VCCA) U2.21(VCC_D) U2.28(VREG)
XTAL12_IN: C22.2 U2.10(XIN) X1.3(Y3)
XTAL12_OUT: C23.2 U2.11(XOUT) X1.1(Y1)

Not connected (* = marked no-connect by the designer): FID1 1*; FID2 1*; FID3 1*; FID4 1*; FID5 1*; FID6 1*; J2 3(R)*; J4 14(NC)*; P7 4(ID)*; P8 2* 4* 5* 6* 7*; P15 8(nPWR_DN)* 30(MCLK)* 33(AFTR_RST)* 34(OE)* 35(SNPSHT)* 37(N~{C})* 38(NC)* 39(NC)* 40(NC)*; P18 19* 20* 21* 23* 27*; RN4 8(R7)* 9(R8)*; RN6 2(RB1)* 7(RB2)*; RN7 2(RB1)* 3(RC1)* 6(RC2)* 7(RB2)*; RN16 5(RD2)*; RN17 1(RA1)* 8(RA2)*; U4 1(RI)* 10(NC)* 11(GPIO3)* 12(GPIO2)* 13(GPIO1)* 14(GPIO0)* 15(SUSPEND#)* 17(SUSPEND)* 18(CTS)* 19(RTS)* 22(DSR)* 23(DTR)* 24(DCD)*; U5 3(IO2)* 5(VBUS)*; U6 7(T2OUT)* 8(T3OUT)* 9(NC)* 13(R5OUT)* 14(R4OUT)* 15(R3OUT)* 16(NC)* 17(R2OUT)* 19(R2OUTB)* 20(INVALID)* 25(NC)* 32(NC)*; U10 1(IO1)* 3(IO2)*; U30 14(I/O1.4)*; U35 5(Vref)*

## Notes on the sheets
sheet 1
- SECONDARY ETHERNET RJ-45
- DNP
- PRIMARY CoM/SoM ETHERNET RJ45
- DNP
- Can be utilized only when CoM is CM-T43
  And Carrier is SB-SOM-T43
- DO NOT
  POPULATE
  FOR:
  SB-SOM-T43
- DNP
- LEDs are active high only (this port is only used with CM-T43)
- DNP
- PARALLEL CAMERA INTERFACE
  OPTIONS
- POWER/RESET/BOOT SWITCHES
- SODIMM165_PWRON:
  T43 (pulled to VCC_CM on SoM):
        HIGH --> LOW = SoM wake/pwron event
        held low for more than 8s/15s = SoM power-cycle
        constantly LOW = constant SoM power-cycling (8s/15s  cycles)
  T54  (pulled to VCC_CM on SoM PMIC):
        HIGH --> LOW = PMIC Interrupt to CPU
        low for more than 15mS = SoM wake/pwron request
        held low for more than 12s = SoM power-off request
  QS600 (pulled high on SoM):
        ON and OFF requests can be triggered
        upon voltage sensed by CM-QS600 here.
- DNP
- DO NOT
  POPULATE
  FOR:
  SB-SOM-QS600
- CM_FLASH_nWP:
  T43 (pulled HIGH on SoM)
        LOW - CoM EEPROM & SPI FLASH write protection enabled/allowed respectively
        HIGH - CoM EEPROM & SPI FLASH write protection disabled
  T54 (pulled HIGH on SoM)
        LOW - CoM EEPROM write protection disabled
        HIGH - CoM EEPROM write protection enabled
  QS600 (VREF_BATT signal. must never be grounded)
        CM-QS600 onboard EEPROM always writeable
- VIP_ADP 40pin FPC
  DEFAULT: NOT POPULATED
- DO NOT
  POPULATE
  FOR:
  SB-SOM-QS600
- ALT_BOOT:
  T43 (pulled LOW on SoM)
        LOW - normal boot sequence
        HIGH - alternative boot sequence
  T54  (pulled LOW on SoM)
        LOW - normal boot sequence
        HIGH - alternative boot sequence
  QS600 (no pull on SOM)
        HIGH - normal boot sequence
        LOW - alternative boot sequence
- DNP
- NOTE: it is not clear whether DATA_EN
   is the same as WEN signal,
   so R42 is DNP by default
- PINOUT SIMILAR TO SB-FX6
- 100MIL header
  DEFAULT: POPULATED
sheet 2
- BOARD REVISION: 1.0
- 1. Initial Revision with support for the following SoMs:
  1.1. CM-T43
  1.2. CM-T54
  1.3. CM-QS600
sheet 3
- LVDS HEADER
- CoM NATIVE HDMI
- DO NOT
  POPULATE
  FOR:
  SB-SOM-T43
- PINOUT SIMILAR TO SB-FX6/SB-T54
- DO NOT
  POPULATE
  FOR:
  SB-SOM-T54
  SB-SOM-QS600
- DO NOT
  POPULATE
  FOR:
  SB-SOM-T43
- Circuitry is designed to shift
  HDMI CEC signal logic levels between
  VSB_PER (1.8 or 3.3V) and 5V.
- DO NOT
  POPULATE
  FOR:
  SB-SOM-T43
- Circuitry is designed to safely shift
  HDMI HOTPLUG signal logic
  levels between
  VSB_PER (1.8 or 3.3V) and 5V.
- CAN TRANSCEIVER
- Circuitry is designed to shift
  DDC signals logic levels between
  VSB_PER (1.8 or 3.3V) and 5V.
sheet 4
- SB-SOM
- BOARD REVISION: 1.0
- PAGE
- DESCRIPTION
- 01
- Index
- 02
- Board Revision History
- 03
- CompuLab CoM/SoM Interface
- 04
- Debug Interface
- 05
- Parallel Display Interface
- 06
- HDMI & LVDS
- 07
- PCIE & SATA
- 08
- USB & Headers
- 09
- Camera & Ethernet
- 10
- Power
- 11
- Bypass: non-SoM-Specific
- 12
- Bypass: CM-T54 Specific
- 13
- Bypass: CM-QS600 Specific
- 14
- Bypass: CM-T43 Specific
- 15
- Bypass: Future SoM/CoMs
- CARRIER BOARD PRIMARY I2C BUS SLAVES (7bit address):
  ----------------------------------------------------------------
  0b010,0000 - Carrier GPIO Expander
  0b011,0110 - DS2786 Battery Supervisor
  0b011,1000 - DVI Transmitter
  0b101,0000 - Carrier ID EEPROM
  0b110,1011 - BQ24161 battery charger & power-path
  0b110,1110 - PCI-E REFCLK fanout
sheet 5
- VBUS SOURCE
- USB OTG
- DO NOT
  POPULATE
  FOR:
  SB-SOM-QS600
  SB-SOM-T43
- DO NOT
  POPULATE
  FOR:
  SB-SOM-QS600
- DNP
- DNP
- DNP
- DO NOT
  POPULATE
  FOR:
  SB-SOM-T43
  SB-SOM-QS600
- DNP
- AUXILIARY 100MIL HEADERS
- DO NOT
  POPULATE
  FOR:
  SB-SOM-QS600
- DO NOT
  POPULATE
  FOR:
  SB-SOM-T43
- CARRIER
  USB2.0 HUB
- SoM/CoM USB2.0 usage selecor
  (P26 or USB Hub upstream port)
- DNP
- DNP
- DNP
- CP
- CP
- DNP
- DNP
- DNP
- DO NOT
  POPULATE
  FOR:
  SB-SOM-QS600
- DNP
- H0.8
- Jumper Populated:
      VBUS1_HUB disconnected from VBUS1
      VBUS1_CON = VBUS1 = 5V
      USBMUX_SEL = 0V ==> USB routed to HSD1 (P26)
  Jumper NOT Populated:
      VBUS1_CON disconnected from VBUS1
      VBUS1_HUB = VBUS1 = 5V
      USBMUX_SEL = VSB_3V3 = 3.3V ==> USB routed to HSD2 (onboard HUB)
- DNP
- DNP
- DNP
- DNP
- DNP
- NOTE:
  USBMUX_SEL signal will only change state after
  VBUS1_CON rail goes high/low enough. This behavior is
  intentional to make sure downstream device (P26/U2)
  receives VBUS before diff signals are "attached".
sheet 6
- CARRIER BOARD PRIMARY I2C BUS LEVEL SHIFT
- PRIMARY SERIAL
  DEBUG PORT
- Circuitry is designed to shift
   I2C signals logic levels between
  VSB_PER (1.8 or 3.3V) and 3.3V.
- NOTE: In case CoM/SoM I/O is @ 3.3V
  levels, such as (CM-T43) level shifting is
  not required. We use level shifting here
  only to be compatible with  non-3.3V I/O
  CoMs (such as CM-T54 or CM-QS600)
- DNP
- DEBUG PORT
  (microUSB2.0 Type B)
  UART over USB
- DO NOT
  POPULATE
  FOR:
  SB-SOM-T43
  SB-SOM-T54
- DNP
- DNP
- Jumper removed: Automatic Mode
      Debug over USB when USB host
  provides VBUS
      Debug over RS-232 when USB VBUS not
  available
  Jumper assembled: Force RS232
      Debug always over RS-232
  NOTE:
  SB-SOM-T54 supports debug over RS-232
  only
- DO NOT
  POPULATE
  FOR:
  SB-SOM-T54
- FULL SIZE SD SLOT
  (BOOTABLE)
- DNP
- DNP
- DO NOT
  POPULATE
  FOR:
  SB-SOM-T54
- DEBUG PORT
  (Compulab Proprietry)
  UART over RS-232
- ANALOG
  AUDIO
- AUDIO OUT
- DO NOT
  POPULATE
  FOR:
  SB-SOM-T43
  SB-SOM-QS600
- MIC.IN
- LINE IN
- CARRIER BOARD EEPROM
- CARRIER GPIO EXPANDER
- DO NOT
  POPULATE
  FOR:
  SB-SOM-QS600
- 7-bit I2C address:
  0b010,0000
- DNP
- DNP
- DNP
- DNP
- Populate jumper to write protect
  carrier board eeprom
- DNP
- DNP
- DNP
- 7-bit I2C address:
  0b101,0000
